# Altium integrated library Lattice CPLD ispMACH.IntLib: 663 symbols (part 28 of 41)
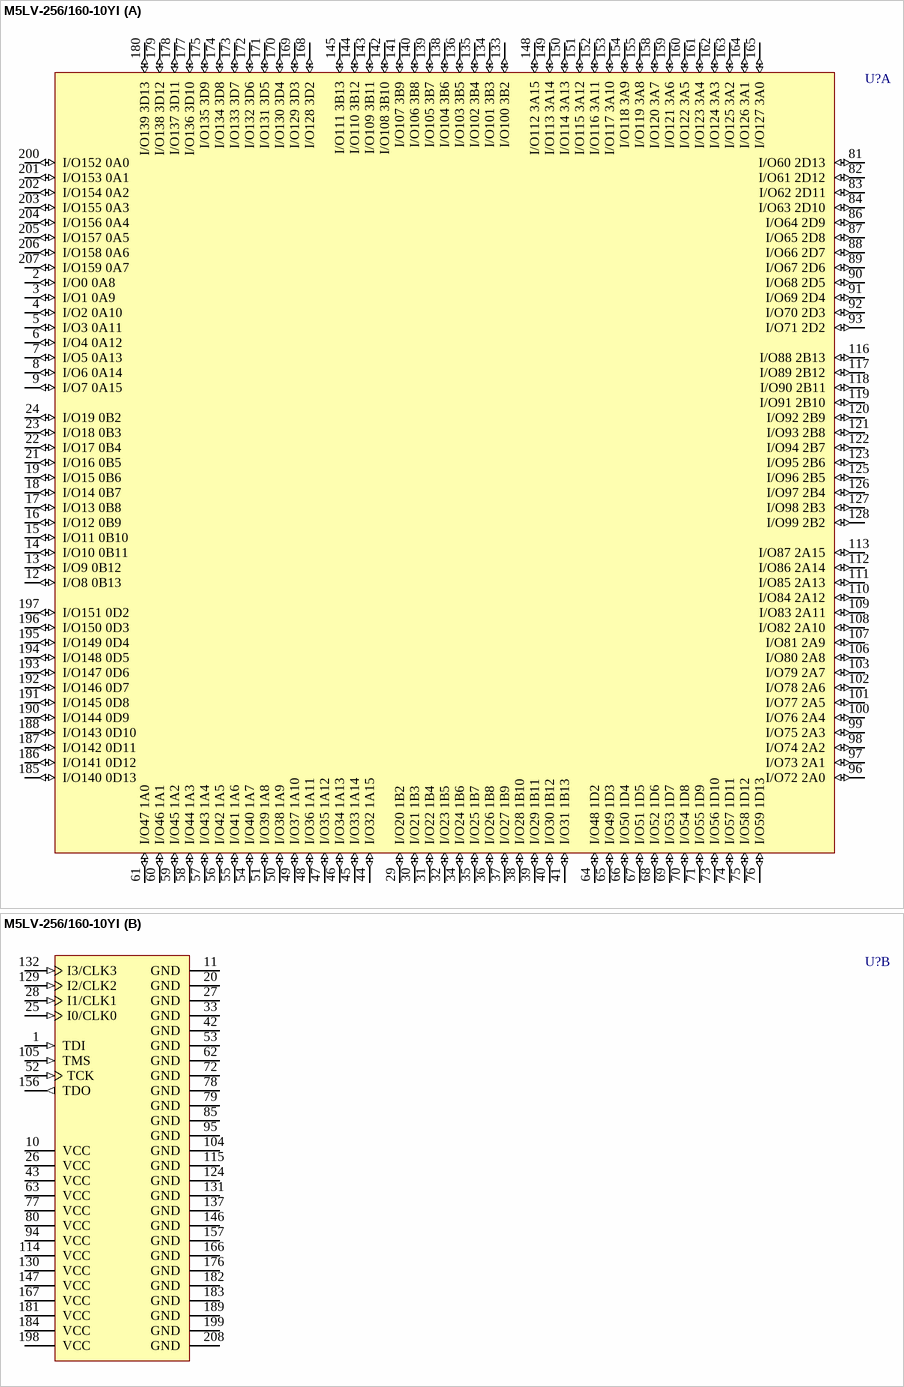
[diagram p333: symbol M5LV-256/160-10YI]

## M5LV-256/160-10YI
designator U?
High-Density and High-I/O Complex PLD
footprint PQFP208_N (Shrink QFP, 208-Leads, Body 28x28mm, Pitch 0.5mm, IPC Medium Density)
footprint PQFP208_L (Shrink QFP, 208-Leads, Body 28x28mm, Pitch 0.5mm, IPC High Density)
footprint PQFP208_M (Shrink QFP, 208-Leads, Body 28x28mm, Pitch 0.5mm, IPC Low Density)
3D model M5LV-PQFP208 (208-Pin Plastic Quad Flat Pack (PQFP208))
part A pins: 2 I/O0 0A8 (io), 3 I/O1 0A9 (io), 4 I/O2 0A10 (io), 5 I/O3 0A11 (io), 6 I/O4 0A12 (io), 7 I/O5 0A13 (io), 8 I/O6 0A14 (io), 9 I/O7 0A15 (io), 12 I/O8 0B13 (io), 13 I/O9 0B12 (io), 14 I/O10 0B11 (io), 15 I/O11 0B10 (io), 16 I/O12 0B9 (io), 17 I/O13 0B8 (io), 18 I/O14 0B7 (io), 19 I/O15 0B6 (io), 21 I/O16 0B5 (io), 22 I/O17 0B4 (io), 23 I/O18 0B3 (io), 24 I/O19 0B2 (io), 29 I/O20 1B2 (io), 30 I/O21 1B3 (io), 31 I/O22 1B4 (io), 32 I/O23 1B5 (io), 34 I/O24 1B6 (io), 35 I/O25 1B7 (io), 36 I/O26 1B8 (io), 37 I/O27 1B9 (io), 38 I/O28 1B10 (io), 39 I/O29 1B11 (io), 40 I/O30 1B12 (io), 41 I/O31 1B13 (io), 44 I/O32 1A15 (io), 45 I/O33 1A14 (io), 46 I/O34 1A13 (io), 47 I/O35 1A12 (io), 48 I/O36 1A11 (io), 49 I/O37 1A10 (io), 50 I/O38 1A9 (io), 51 I/O39 1A8 (io), 54 I/O40 1A7 (io), 55 I/O41 1A6 (io), 56 I/O42 1A5 (io), 57 I/O43 1A4 (io), 58 I/O44 1A3 (io), 59 I/O45 1A2 (io), 60 I/O46 1A1 (io), 61 I/O47 1A0 (io), 64 I/O48 1D2 (io), 65 I/O49 1D3 (io), 66 I/O50 1D4 (io), 67 I/O51 1D5 (io), 68 I/O52 1D6 (io), 69 I/O53 1D7 (io), 70 I/O54 1D8 (io), 71 I/O55 1D9 (io), 73 I/O56 1D10 (io), 74 I/O57 1D11 (io), 75 I/O58 1D12 (io), 76 I/O59 1D13 (io), 81 I/O60 2D13 (io), 82 I/O61 2D12 (io), 83 I/O62 2D11 (io), 84 I/O63 2D10 (io), 86 I/O64 2D9 (io), 87 I/O65 2D8 (io), 88 I/O66 2D7 (io), 89 I/O67 2D6 (io), 90 I/O68 2D5 (io), 91 I/O69 2D4 (io), 92 I/O70 2D3 (io), 93 I/O71 2D2 (io), 96 I/O72 2A0 (io), 97 I/O73 2A1 (io), 98 I/O74 2A2 (io), 99 I/O75 2A3 (io), 100 I/O76 2A4 (io), 101 I/O77 2A5 (io), 102 I/O78 2A6 (io), 103 I/O79 2A7 (io), 106 I/O80 2A8 (io), 107 I/O81 2A9 (io), 108 I/O82 2A10 (io), 109 I/O83 2A11 (io), 110 I/O84 2A12 (io), 111 I/O85 2A13 (io), 112 I/O86 2A14 (io), 113 I/O87 2A15 (io), 116 I/O88 2B13 (io), 117 I/O89 2B12 (io), 118 I/O90 2B11 (io), 119 I/O91 2B10 (io), 120 I/O92 2B9 (io), 121 I/O93 2B8 (io), 122 I/O94 2B7 (io), 123 I/O95 2B6 (io), 125 I/O96 2B5 (io), 126 I/O97 2B4 (io), 127 I/O98 2B3 (io), 128 I/O99 2B2 (io), 133 I/O100 3B2 (io), 134 I/O101 3B3 (io), 135 I/O102 3B4 (io), 136 I/O103 3B5 (io), 138 I/O104 3B6 (io), 139 I/O105 3B7 (io), 140 I/O106 3B8 (io), 141 I/O107 3B9 (io), 142 I/O108 3B10 (io), 143 I/O109 3B11 (io), 144 I/O110 3B12 (io), 145 I/O111 3B13 (io), 148 I/O112 3A15 (io), 149 I/O113 3A14 (io), 150 I/O114 3A13 (io), 151 I/O115 3A12 (io), 152 I/O116 3A11 (io), 153 I/O117 3A10 (io), 154 I/O118 3A9 (io), 155 I/O119 3A8 (io), 158 I/O120 3A7 (io), 159 I/O121 3A6 (io), 160 I/O122 3A5 (io), 161 I/O123 3A4 (io), 162 I/O124 3A3 (io), 163 I/O125 3A2 (io), 164 I/O126 3A1 (io), 165 I/O127 3A0 (io), 168 I/O128 3D2 (io), 169 I/O129 3D3 (io), 170 I/O130 3D4 (io), 171 I/O131 3D5 (io), 172 I/O132 3D6 (io), 173 I/O133 3D7 (io), 174 I/O134 3D8 (io), 175 I/O135 3D9 (io), 177 I/O136 3D10 (io), 178 I/O137 3D11 (io), 179 I/O138 3D12 (io), 180 I/O139 3D13 (io), 185 I/O140 0D13 (io), 186 I/O141 0D12 (io), 187 I/O142 0D11 (io), 188 I/O143 0D10 (io), 190 I/O144 0D9 (io), 191 I/O145 0D8 (io), 192 I/O146 0D7 (io), 193 I/O147 0D6 (io), 194 I/O148 0D5 (io), 195 I/O149 0D4 (io), 196 I/O150 0D3 (io), 197 I/O151 0D2 (io), 200 I/O152 0A0 (io), 201 I/O153 0A1 (io), 202 I/O154 0A2 (io), 203 I/O155 0A3 (io), 204 I/O156 0A4 (io), 205 I/O157 0A5 (io), 206 I/O158 0A6 (io), 207 I/O159 0A7 (io)
part B pins: 1 TDI (in), 10 VCC (power), 11 GND (power), 20 GND (power), 25 I0/CLK0 (in), 26 VCC (power), 27 GND (power), 28 I1/CLK1 (in), 33 GND (power), 42 GND (power), 43 VCC (power), 52 TCK (in), 53 GND (power), 62 GND (power), 63 VCC (power), 72 GND (power), 77 VCC (power), 78 GND (power), 79 GND (power), 80 VCC (power), 85 GND (power), 94 VCC (power), 95 GND (power), 104 GND (power), 105 TMS (in), 114 VCC (power), 115 GND (power), 124 GND (power), 129 I2/CLK2 (in), 130 VCC (power), 131 GND (power), 132 I3/CLK3 (in), 137 GND (power), 146 GND (power), 147 VCC (power), 156 TDO (out), 157 GND (power), 166 GND (power), 167 VCC (power), 176 GND (power), 181 VCC (power), 182 GND (power), 183 GND (power), 184 VCC (power), 189 GND (power), 198 VCC (power), 199 GND (power), 208 GND (power)

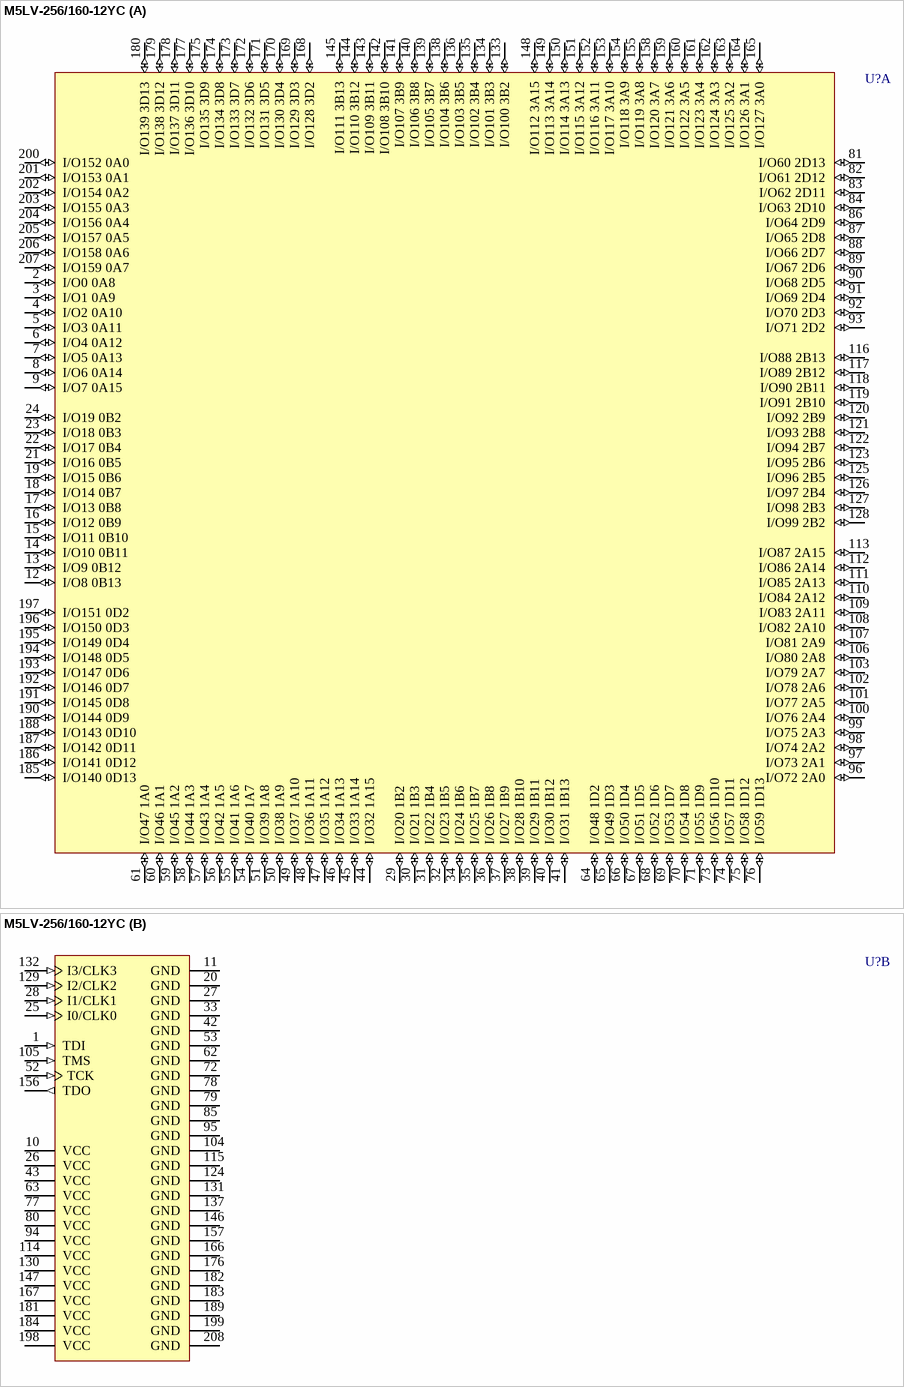
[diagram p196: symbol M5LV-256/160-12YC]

## M5LV-256/160-12YC
designator U?
High-Density and High-I/O Complex PLD
footprint PQFP208_N (Shrink QFP, 208-Leads, Body 28x28mm, Pitch 0.5mm, IPC Medium Density)
footprint PQFP208_L (Shrink QFP, 208-Leads, Body 28x28mm, Pitch 0.5mm, IPC High Density)
footprint PQFP208_M (Shrink QFP, 208-Leads, Body 28x28mm, Pitch 0.5mm, IPC Low Density)
3D model M5LV-PQFP208 (208-Pin Plastic Quad Flat Pack (PQFP208))
part A pins: 2 I/O0 0A8 (io), 3 I/O1 0A9 (io), 4 I/O2 0A10 (io), 5 I/O3 0A11 (io), 6 I/O4 0A12 (io), 7 I/O5 0A13 (io), 8 I/O6 0A14 (io), 9 I/O7 0A15 (io), 12 I/O8 0B13 (io), 13 I/O9 0B12 (io), 14 I/O10 0B11 (io), 15 I/O11 0B10 (io), 16 I/O12 0B9 (io), 17 I/O13 0B8 (io), 18 I/O14 0B7 (io), 19 I/O15 0B6 (io), 21 I/O16 0B5 (io), 22 I/O17 0B4 (io), 23 I/O18 0B3 (io), 24 I/O19 0B2 (io), 29 I/O20 1B2 (io), 30 I/O21 1B3 (io), 31 I/O22 1B4 (io), 32 I/O23 1B5 (io), 34 I/O24 1B6 (io), 35 I/O25 1B7 (io), 36 I/O26 1B8 (io), 37 I/O27 1B9 (io), 38 I/O28 1B10 (io), 39 I/O29 1B11 (io), 40 I/O30 1B12 (io), 41 I/O31 1B13 (io), 44 I/O32 1A15 (io), 45 I/O33 1A14 (io), 46 I/O34 1A13 (io), 47 I/O35 1A12 (io), 48 I/O36 1A11 (io), 49 I/O37 1A10 (io), 50 I/O38 1A9 (io), 51 I/O39 1A8 (io), 54 I/O40 1A7 (io), 55 I/O41 1A6 (io), 56 I/O42 1A5 (io), 57 I/O43 1A4 (io), 58 I/O44 1A3 (io), 59 I/O45 1A2 (io), 60 I/O46 1A1 (io), 61 I/O47 1A0 (io), 64 I/O48 1D2 (io), 65 I/O49 1D3 (io), 66 I/O50 1D4 (io), 67 I/O51 1D5 (io), 68 I/O52 1D6 (io), 69 I/O53 1D7 (io), 70 I/O54 1D8 (io), 71 I/O55 1D9 (io), 73 I/O56 1D10 (io), 74 I/O57 1D11 (io), 75 I/O58 1D12 (io), 76 I/O59 1D13 (io), 81 I/O60 2D13 (io), 82 I/O61 2D12 (io), 83 I/O62 2D11 (io), 84 I/O63 2D10 (io), 86 I/O64 2D9 (io), 87 I/O65 2D8 (io), 88 I/O66 2D7 (io), 89 I/O67 2D6 (io), 90 I/O68 2D5 (io), 91 I/O69 2D4 (io), 92 I/O70 2D3 (io), 93 I/O71 2D2 (io), 96 I/O72 2A0 (io), 97 I/O73 2A1 (io), 98 I/O74 2A2 (io), 99 I/O75 2A3 (io), 100 I/O76 2A4 (io), 101 I/O77 2A5 (io), 102 I/O78 2A6 (io), 103 I/O79 2A7 (io), 106 I/O80 2A8 (io), 107 I/O81 2A9 (io), 108 I/O82 2A10 (io), 109 I/O83 2A11 (io), 110 I/O84 2A12 (io), 111 I/O85 2A13 (io), 112 I/O86 2A14 (io), 113 I/O87 2A15 (io), 116 I/O88 2B13 (io), 117 I/O89 2B12 (io), 118 I/O90 2B11 (io), 119 I/O91 2B10 (io), 120 I/O92 2B9 (io), 121 I/O93 2B8 (io), 122 I/O94 2B7 (io), 123 I/O95 2B6 (io), 125 I/O96 2B5 (io), 126 I/O97 2B4 (io), 127 I/O98 2B3 (io), 128 I/O99 2B2 (io), 133 I/O100 3B2 (io), 134 I/O101 3B3 (io), 135 I/O102 3B4 (io), 136 I/O103 3B5 (io), 138 I/O104 3B6 (io), 139 I/O105 3B7 (io), 140 I/O106 3B8 (io), 141 I/O107 3B9 (io), 142 I/O108 3B10 (io), 143 I/O109 3B11 (io), 144 I/O110 3B12 (io), 145 I/O111 3B13 (io), 148 I/O112 3A15 (io), 149 I/O113 3A14 (io), 150 I/O114 3A13 (io), 151 I/O115 3A12 (io), 152 I/O116 3A11 (io), 153 I/O117 3A10 (io), 154 I/O118 3A9 (io), 155 I/O119 3A8 (io), 158 I/O120 3A7 (io), 159 I/O121 3A6 (io), 160 I/O122 3A5 (io), 161 I/O123 3A4 (io), 162 I/O124 3A3 (io), 163 I/O125 3A2 (io), 164 I/O126 3A1 (io), 165 I/O127 3A0 (io), 168 I/O128 3D2 (io), 169 I/O129 3D3 (io), 170 I/O130 3D4 (io), 171 I/O131 3D5 (io), 172 I/O132 3D6 (io), 173 I/O133 3D7 (io), 174 I/O134 3D8 (io), 175 I/O135 3D9 (io), 177 I/O136 3D10 (io), 178 I/O137 3D11 (io), 179 I/O138 3D12 (io), 180 I/O139 3D13 (io), 185 I/O140 0D13 (io), 186 I/O141 0D12 (io), 187 I/O142 0D11 (io), 188 I/O143 0D10 (io), 190 I/O144 0D9 (io), 191 I/O145 0D8 (io), 192 I/O146 0D7 (io), 193 I/O147 0D6 (io), 194 I/O148 0D5 (io), 195 I/O149 0D4 (io), 196 I/O150 0D3 (io), 197 I/O151 0D2 (io), 200 I/O152 0A0 (io), 201 I/O153 0A1 (io), 202 I/O154 0A2 (io), 203 I/O155 0A3 (io), 204 I/O156 0A4 (io), 205 I/O157 0A5 (io), 206 I/O158 0A6 (io), 207 I/O159 0A7 (io)
part B pins: 1 TDI (in), 10 VCC (power), 11 GND (power), 20 GND (power), 25 I0/CLK0 (in), 26 VCC (power), 27 GND (power), 28 I1/CLK1 (in), 33 GND (power), 42 GND (power), 43 VCC (power), 52 TCK (in), 53 GND (power), 62 GND (power), 63 VCC (power), 72 GND (power), 77 VCC (power), 78 GND (power), 79 GND (power), 80 VCC (power), 85 GND (power), 94 VCC (power), 95 GND (power), 104 GND (power), 105 TMS (in), 114 VCC (power), 115 GND (power), 124 GND (power), 129 I2/CLK2 (in), 130 VCC (power), 131 GND (power), 132 I3/CLK3 (in), 137 GND (power), 146 GND (power), 147 VCC (power), 156 TDO (out), 157 GND (power), 166 GND (power), 167 VCC (power), 176 GND (power), 181 VCC (power), 182 GND (power), 183 GND (power), 184 VCC (power), 189 GND (power), 198 VCC (power), 199 GND (power), 208 GND (power)

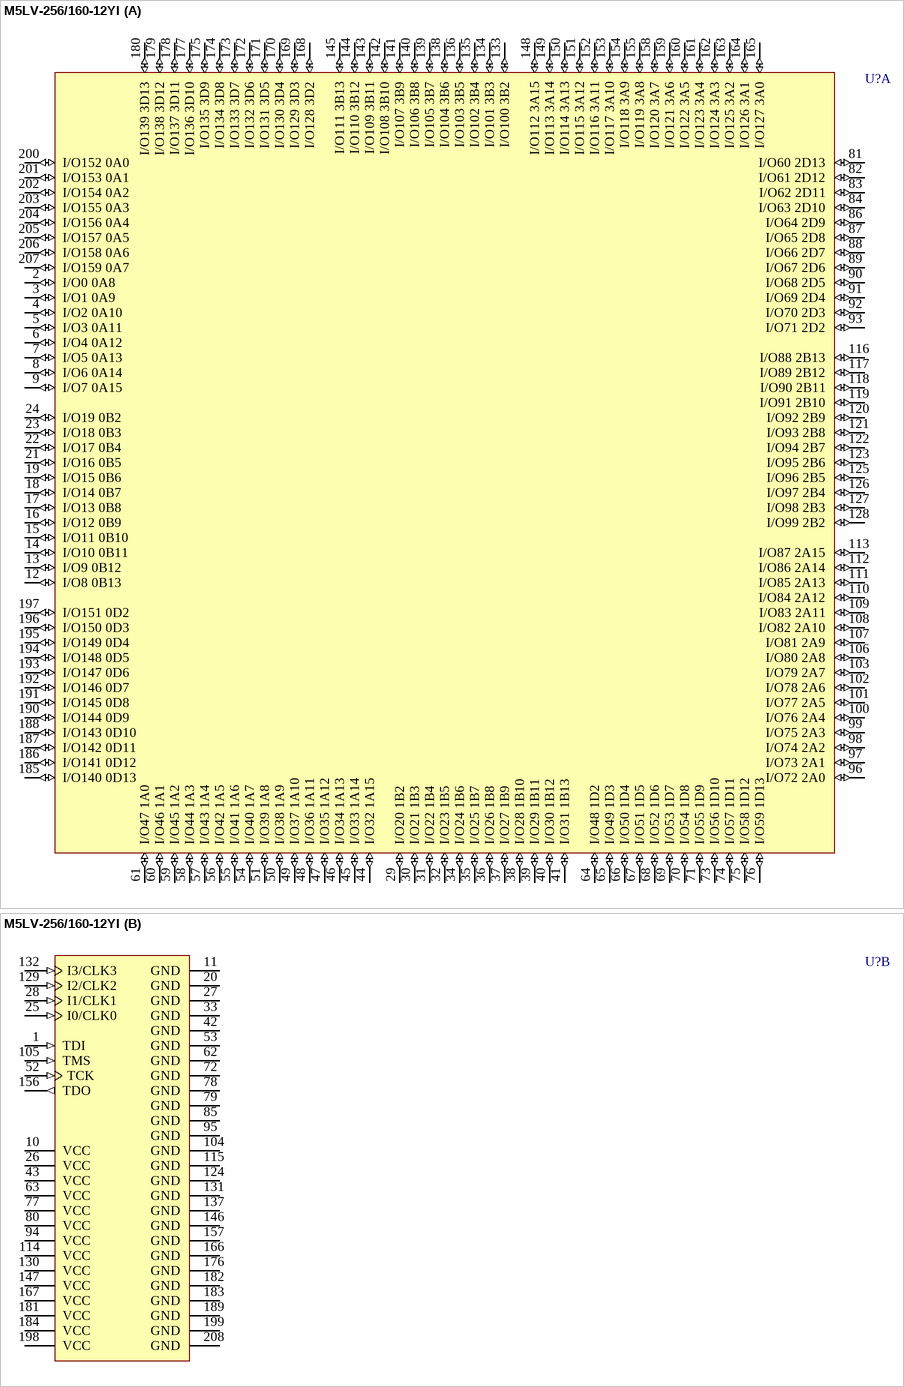
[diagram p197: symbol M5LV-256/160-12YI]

## M5LV-256/160-12YI
designator U?
High-Density and High-I/O Complex PLD
footprint PQFP208_N (Shrink QFP, 208-Leads, Body 28x28mm, Pitch 0.5mm, IPC Medium Density)
footprint PQFP208_L (Shrink QFP, 208-Leads, Body 28x28mm, Pitch 0.5mm, IPC High Density)
footprint PQFP208_M (Shrink QFP, 208-Leads, Body 28x28mm, Pitch 0.5mm, IPC Low Density)
3D model M5LV-PQFP208 (208-Pin Plastic Quad Flat Pack (PQFP208))
part A pins: 2 I/O0 0A8 (io), 3 I/O1 0A9 (io), 4 I/O2 0A10 (io), 5 I/O3 0A11 (io), 6 I/O4 0A12 (io), 7 I/O5 0A13 (io), 8 I/O6 0A14 (io), 9 I/O7 0A15 (io), 12 I/O8 0B13 (io), 13 I/O9 0B12 (io), 14 I/O10 0B11 (io), 15 I/O11 0B10 (io), 16 I/O12 0B9 (io), 17 I/O13 0B8 (io), 18 I/O14 0B7 (io), 19 I/O15 0B6 (io), 21 I/O16 0B5 (io), 22 I/O17 0B4 (io), 23 I/O18 0B3 (io), 24 I/O19 0B2 (io), 29 I/O20 1B2 (io), 30 I/O21 1B3 (io), 31 I/O22 1B4 (io), 32 I/O23 1B5 (io), 34 I/O24 1B6 (io), 35 I/O25 1B7 (io), 36 I/O26 1B8 (io), 37 I/O27 1B9 (io), 38 I/O28 1B10 (io), 39 I/O29 1B11 (io), 40 I/O30 1B12 (io), 41 I/O31 1B13 (io), 44 I/O32 1A15 (io), 45 I/O33 1A14 (io), 46 I/O34 1A13 (io), 47 I/O35 1A12 (io), 48 I/O36 1A11 (io), 49 I/O37 1A10 (io), 50 I/O38 1A9 (io), 51 I/O39 1A8 (io), 54 I/O40 1A7 (io), 55 I/O41 1A6 (io), 56 I/O42 1A5 (io), 57 I/O43 1A4 (io), 58 I/O44 1A3 (io), 59 I/O45 1A2 (io), 60 I/O46 1A1 (io), 61 I/O47 1A0 (io), 64 I/O48 1D2 (io), 65 I/O49 1D3 (io), 66 I/O50 1D4 (io), 67 I/O51 1D5 (io), 68 I/O52 1D6 (io), 69 I/O53 1D7 (io), 70 I/O54 1D8 (io), 71 I/O55 1D9 (io), 73 I/O56 1D10 (io), 74 I/O57 1D11 (io), 75 I/O58 1D12 (io), 76 I/O59 1D13 (io), 81 I/O60 2D13 (io), 82 I/O61 2D12 (io), 83 I/O62 2D11 (io), 84 I/O63 2D10 (io), 86 I/O64 2D9 (io), 87 I/O65 2D8 (io), 88 I/O66 2D7 (io), 89 I/O67 2D6 (io), 90 I/O68 2D5 (io), 91 I/O69 2D4 (io), 92 I/O70 2D3 (io), 93 I/O71 2D2 (io), 96 I/O72 2A0 (io), 97 I/O73 2A1 (io), 98 I/O74 2A2 (io), 99 I/O75 2A3 (io), 100 I/O76 2A4 (io), 101 I/O77 2A5 (io), 102 I/O78 2A6 (io), 103 I/O79 2A7 (io), 106 I/O80 2A8 (io), 107 I/O81 2A9 (io), 108 I/O82 2A10 (io), 109 I/O83 2A11 (io), 110 I/O84 2A12 (io), 111 I/O85 2A13 (io), 112 I/O86 2A14 (io), 113 I/O87 2A15 (io), 116 I/O88 2B13 (io), 117 I/O89 2B12 (io), 118 I/O90 2B11 (io), 119 I/O91 2B10 (io), 120 I/O92 2B9 (io), 121 I/O93 2B8 (io), 122 I/O94 2B7 (io), 123 I/O95 2B6 (io), 125 I/O96 2B5 (io), 126 I/O97 2B4 (io), 127 I/O98 2B3 (io), 128 I/O99 2B2 (io), 133 I/O100 3B2 (io), 134 I/O101 3B3 (io), 135 I/O102 3B4 (io), 136 I/O103 3B5 (io), 138 I/O104 3B6 (io), 139 I/O105 3B7 (io), 140 I/O106 3B8 (io), 141 I/O107 3B9 (io), 142 I/O108 3B10 (io), 143 I/O109 3B11 (io), 144 I/O110 3B12 (io), 145 I/O111 3B13 (io), 148 I/O112 3A15 (io), 149 I/O113 3A14 (io), 150 I/O114 3A13 (io), 151 I/O115 3A12 (io), 152 I/O116 3A11 (io), 153 I/O117 3A10 (io), 154 I/O118 3A9 (io), 155 I/O119 3A8 (io), 158 I/O120 3A7 (io), 159 I/O121 3A6 (io), 160 I/O122 3A5 (io), 161 I/O123 3A4 (io), 162 I/O124 3A3 (io), 163 I/O125 3A2 (io), 164 I/O126 3A1 (io), 165 I/O127 3A0 (io), 168 I/O128 3D2 (io), 169 I/O129 3D3 (io), 170 I/O130 3D4 (io), 171 I/O131 3D5 (io), 172 I/O132 3D6 (io), 173 I/O133 3D7 (io), 174 I/O134 3D8 (io), 175 I/O135 3D9 (io), 177 I/O136 3D10 (io), 178 I/O137 3D11 (io), 179 I/O138 3D12 (io), 180 I/O139 3D13 (io), 185 I/O140 0D13 (io), 186 I/O141 0D12 (io), 187 I/O142 0D11 (io), 188 I/O143 0D10 (io), 190 I/O144 0D9 (io), 191 I/O145 0D8 (io), 192 I/O146 0D7 (io), 193 I/O147 0D6 (io), 194 I/O148 0D5 (io), 195 I/O149 0D4 (io), 196 I/O150 0D3 (io), 197 I/O151 0D2 (io), 200 I/O152 0A0 (io), 201 I/O153 0A1 (io), 202 I/O154 0A2 (io), 203 I/O155 0A3 (io), 204 I/O156 0A4 (io), 205 I/O157 0A5 (io), 206 I/O158 0A6 (io), 207 I/O159 0A7 (io)
part B pins: 1 TDI (in), 10 VCC (power), 11 GND (power), 20 GND (power), 25 I0/CLK0 (in), 26 VCC (power), 27 GND (power), 28 I1/CLK1 (in), 33 GND (power), 42 GND (power), 43 VCC (power), 52 TCK (in), 53 GND (power), 62 GND (power), 63 VCC (power), 72 GND (power), 77 VCC (power), 78 GND (power), 79 GND (power), 80 VCC (power), 85 GND (power), 94 VCC (power), 95 GND (power), 104 GND (power), 105 TMS (in), 114 VCC (power), 115 GND (power), 124 GND (power), 129 I2/CLK2 (in), 130 VCC (power), 131 GND (power), 132 I3/CLK3 (in), 137 GND (power), 146 GND (power), 147 VCC (power), 156 TDO (out), 157 GND (power), 166 GND (power), 167 VCC (power), 176 GND (power), 181 VCC (power), 182 GND (power), 183 GND (power), 184 VCC (power), 189 GND (power), 198 VCC (power), 199 GND (power), 208 GND (power)

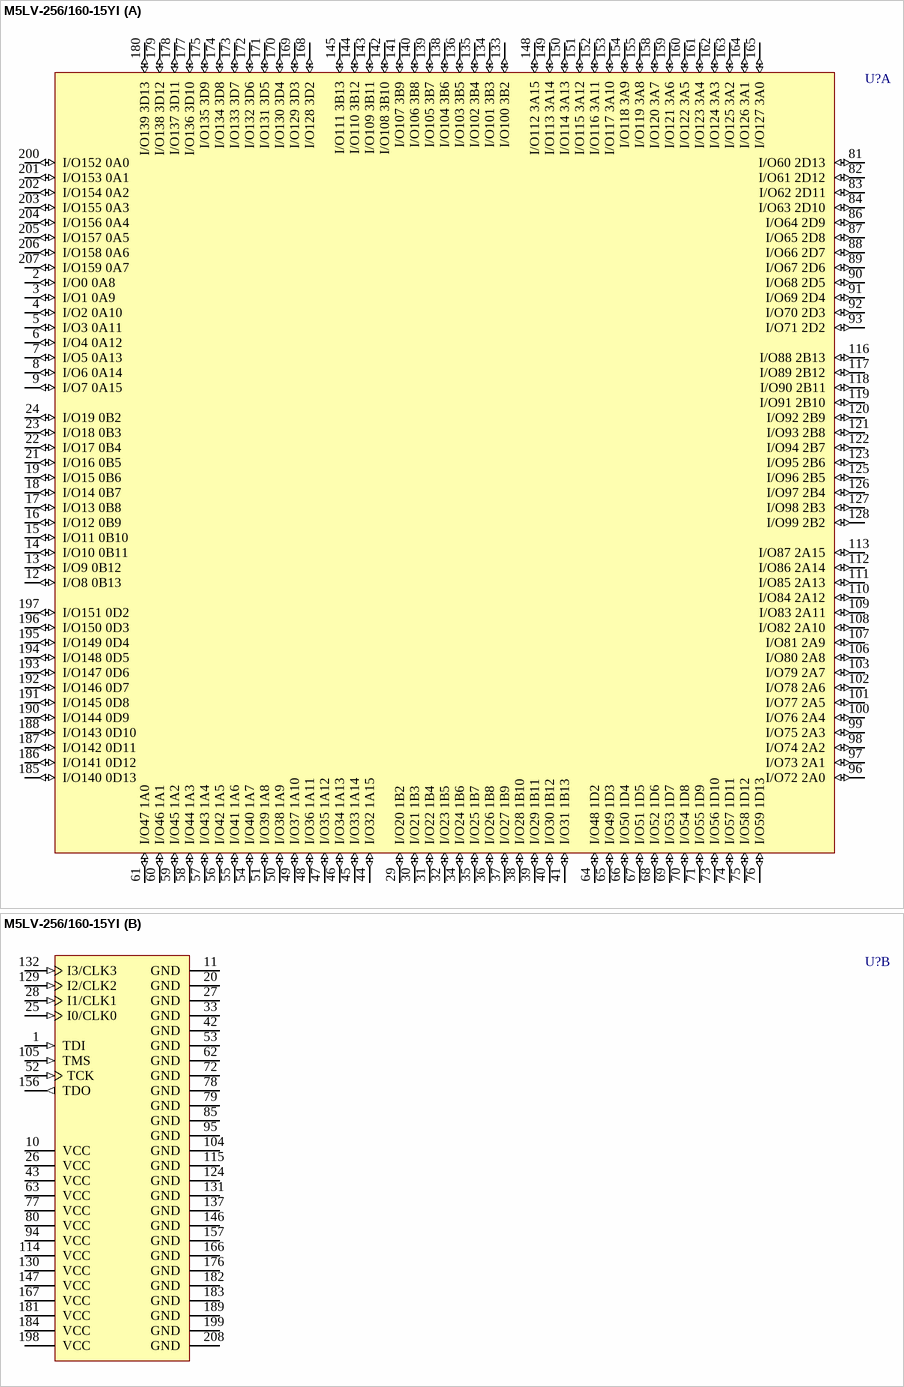
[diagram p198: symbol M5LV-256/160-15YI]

## M5LV-256/160-15YI
designator U?
High-Density and High-I/O Complex PLD
footprint PQFP208_N (Shrink QFP, 208-Leads, Body 28x28mm, Pitch 0.5mm, IPC Medium Density)
footprint PQFP208_L (Shrink QFP, 208-Leads, Body 28x28mm, Pitch 0.5mm, IPC High Density)
footprint PQFP208_M (Shrink QFP, 208-Leads, Body 28x28mm, Pitch 0.5mm, IPC Low Density)
3D model M5LV-PQFP208 (208-Pin Plastic Quad Flat Pack (PQFP208))
part A pins: 2 I/O0 0A8 (io), 3 I/O1 0A9 (io), 4 I/O2 0A10 (io), 5 I/O3 0A11 (io), 6 I/O4 0A12 (io), 7 I/O5 0A13 (io), 8 I/O6 0A14 (io), 9 I/O7 0A15 (io), 12 I/O8 0B13 (io), 13 I/O9 0B12 (io), 14 I/O10 0B11 (io), 15 I/O11 0B10 (io), 16 I/O12 0B9 (io), 17 I/O13 0B8 (io), 18 I/O14 0B7 (io), 19 I/O15 0B6 (io), 21 I/O16 0B5 (io), 22 I/O17 0B4 (io), 23 I/O18 0B3 (io), 24 I/O19 0B2 (io), 29 I/O20 1B2 (io), 30 I/O21 1B3 (io), 31 I/O22 1B4 (io), 32 I/O23 1B5 (io), 34 I/O24 1B6 (io), 35 I/O25 1B7 (io), 36 I/O26 1B8 (io), 37 I/O27 1B9 (io), 38 I/O28 1B10 (io), 39 I/O29 1B11 (io), 40 I/O30 1B12 (io), 41 I/O31 1B13 (io), 44 I/O32 1A15 (io), 45 I/O33 1A14 (io), 46 I/O34 1A13 (io), 47 I/O35 1A12 (io), 48 I/O36 1A11 (io), 49 I/O37 1A10 (io), 50 I/O38 1A9 (io), 51 I/O39 1A8 (io), 54 I/O40 1A7 (io), 55 I/O41 1A6 (io), 56 I/O42 1A5 (io), 57 I/O43 1A4 (io), 58 I/O44 1A3 (io), 59 I/O45 1A2 (io), 60 I/O46 1A1 (io), 61 I/O47 1A0 (io), 64 I/O48 1D2 (io), 65 I/O49 1D3 (io), 66 I/O50 1D4 (io), 67 I/O51 1D5 (io), 68 I/O52 1D6 (io), 69 I/O53 1D7 (io), 70 I/O54 1D8 (io), 71 I/O55 1D9 (io), 73 I/O56 1D10 (io), 74 I/O57 1D11 (io), 75 I/O58 1D12 (io), 76 I/O59 1D13 (io), 81 I/O60 2D13 (io), 82 I/O61 2D12 (io), 83 I/O62 2D11 (io), 84 I/O63 2D10 (io), 86 I/O64 2D9 (io), 87 I/O65 2D8 (io), 88 I/O66 2D7 (io), 89 I/O67 2D6 (io), 90 I/O68 2D5 (io), 91 I/O69 2D4 (io), 92 I/O70 2D3 (io), 93 I/O71 2D2 (io), 96 I/O72 2A0 (io), 97 I/O73 2A1 (io), 98 I/O74 2A2 (io), 99 I/O75 2A3 (io), 100 I/O76 2A4 (io), 101 I/O77 2A5 (io), 102 I/O78 2A6 (io), 103 I/O79 2A7 (io), 106 I/O80 2A8 (io), 107 I/O81 2A9 (io), 108 I/O82 2A10 (io), 109 I/O83 2A11 (io), 110 I/O84 2A12 (io), 111 I/O85 2A13 (io), 112 I/O86 2A14 (io), 113 I/O87 2A15 (io), 116 I/O88 2B13 (io), 117 I/O89 2B12 (io), 118 I/O90 2B11 (io), 119 I/O91 2B10 (io), 120 I/O92 2B9 (io), 121 I/O93 2B8 (io), 122 I/O94 2B7 (io), 123 I/O95 2B6 (io), 125 I/O96 2B5 (io), 126 I/O97 2B4 (io), 127 I/O98 2B3 (io), 128 I/O99 2B2 (io), 133 I/O100 3B2 (io), 134 I/O101 3B3 (io), 135 I/O102 3B4 (io), 136 I/O103 3B5 (io), 138 I/O104 3B6 (io), 139 I/O105 3B7 (io), 140 I/O106 3B8 (io), 141 I/O107 3B9 (io), 142 I/O108 3B10 (io), 143 I/O109 3B11 (io), 144 I/O110 3B12 (io), 145 I/O111 3B13 (io), 148 I/O112 3A15 (io), 149 I/O113 3A14 (io), 150 I/O114 3A13 (io), 151 I/O115 3A12 (io), 152 I/O116 3A11 (io), 153 I/O117 3A10 (io), 154 I/O118 3A9 (io), 155 I/O119 3A8 (io), 158 I/O120 3A7 (io), 159 I/O121 3A6 (io), 160 I/O122 3A5 (io), 161 I/O123 3A4 (io), 162 I/O124 3A3 (io), 163 I/O125 3A2 (io), 164 I/O126 3A1 (io), 165 I/O127 3A0 (io), 168 I/O128 3D2 (io), 169 I/O129 3D3 (io), 170 I/O130 3D4 (io), 171 I/O131 3D5 (io), 172 I/O132 3D6 (io), 173 I/O133 3D7 (io), 174 I/O134 3D8 (io), 175 I/O135 3D9 (io), 177 I/O136 3D10 (io), 178 I/O137 3D11 (io), 179 I/O138 3D12 (io), 180 I/O139 3D13 (io), 185 I/O140 0D13 (io), 186 I/O141 0D12 (io), 187 I/O142 0D11 (io), 188 I/O143 0D10 (io), 190 I/O144 0D9 (io), 191 I/O145 0D8 (io), 192 I/O146 0D7 (io), 193 I/O147 0D6 (io), 194 I/O148 0D5 (io), 195 I/O149 0D4 (io), 196 I/O150 0D3 (io), 197 I/O151 0D2 (io), 200 I/O152 0A0 (io), 201 I/O153 0A1 (io), 202 I/O154 0A2 (io), 203 I/O155 0A3 (io), 204 I/O156 0A4 (io), 205 I/O157 0A5 (io), 206 I/O158 0A6 (io), 207 I/O159 0A7 (io)
part B pins: 1 TDI (in), 10 VCC (power), 11 GND (power), 20 GND (power), 25 I0/CLK0 (in), 26 VCC (power), 27 GND (power), 28 I1/CLK1 (in), 33 GND (power), 42 GND (power), 43 VCC (power), 52 TCK (in), 53 GND (power), 62 GND (power), 63 VCC (power), 72 GND (power), 77 VCC (power), 78 GND (power), 79 GND (power), 80 VCC (power), 85 GND (power), 94 VCC (power), 95 GND (power), 104 GND (power), 105 TMS (in), 114 VCC (power), 115 GND (power), 124 GND (power), 129 I2/CLK2 (in), 130 VCC (power), 131 GND (power), 132 I3/CLK3 (in), 137 GND (power), 146 GND (power), 147 VCC (power), 156 TDO (out), 157 GND (power), 166 GND (power), 167 VCC (power), 176 GND (power), 181 VCC (power), 182 GND (power), 183 GND (power), 184 VCC (power), 189 GND (power), 198 VCC (power), 199 GND (power), 208 GND (power)

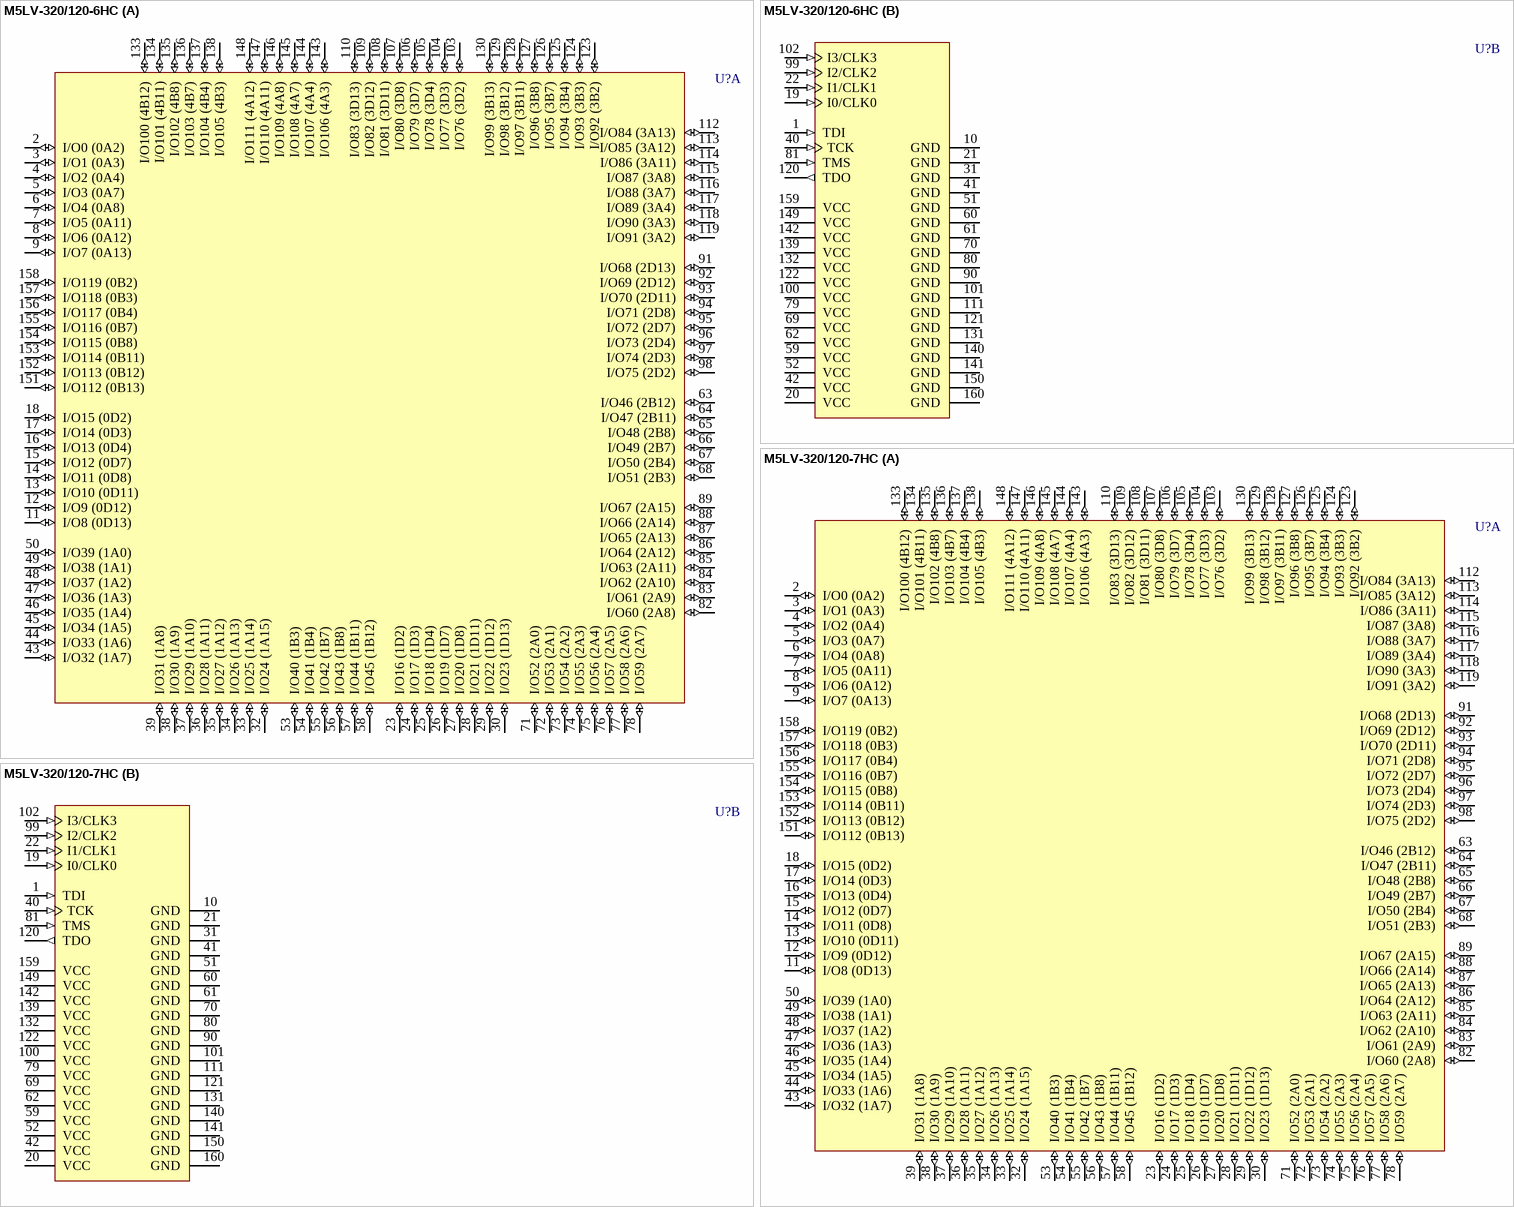
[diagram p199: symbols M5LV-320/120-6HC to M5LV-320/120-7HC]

## M5LV-320/120-6HC
designator U?
High-Density and High-I/O Complex PLD
footprint MQFP160_N (QFP, 160-Leads, Body 27.7 x 27.7mm, Pitch 0.65mm, IPC Medium Density)
footprint MQFP160_L (QFP, 160-Leads, Body 27.7 x 27.7mm, Pitch 0.65mm, IPC High Density)
footprint MQFP160_M (QFP, 160-Leads, Body 27.7 x 27.7mm, Pitch 0.65mm, IPC Low Density)
3D model M5LV-MQFP160 (160-Pin Quad Flat Pack 0.65 mm Pitch)
part A pins: 2 I/O0 (0A2) (io), 3 I/O1 (0A3) (io), 4 I/O2 (0A4) (io), 5 I/O3 (0A7) (io), 6 I/O4 (0A8) (io), 7 I/O5 (0A11) (io), 8 I/O6 (0A12) (io), 9 I/O7 (0A13) (io), 11 I/O8 (0D13) (io), 12 I/O9 (0D12) (io), 13 I/O10 (0D11) (io), 14 I/O11 (0D8) (io), 15 I/O12 (0D7) (io), 16 I/O13 (0D4) (io), 17 I/O14 (0D3) (io), 18 I/O15 (0D2) (io), 23 I/O16 (1D2) (io), 24 I/O17 (1D3) (io), 25 I/O18 (1D4) (io), 26 I/O19 (1D7) (io), 27 I/O20 (1D8) (io), 28 I/O21 (1D11) (io), 29 I/O22 (1D12) (io), 30 I/O23 (1D13) (io), 32 I/O24 (1A15) (io), 33 I/O25 (1A14) (io), 34 I/O26 (1A13) (io), 35 I/O27 (1A12) (io), 36 I/O28 (1A11) (io), 37 I/O29 (1A10) (io), 38 I/O30 (1A9) (io), 39 I/O31 (1A8) (io), 43 I/O32 (1A7) (io), 44 I/O33 (1A6) (io), 45 I/O34 (1A5) (io), 46 I/O35 (1A4) (io), 47 I/O36 (1A3) (io), 48 I/O37 (1A2) (io), 49 I/O38 (1A1) (io), 50 I/O39 (1A0) (io), 53 I/O40 (1B3) (io), 54 I/O41 (1B4) (io), 55 I/O42 (1B7) (io), 56 I/O43 (1B8) (io), 57 I/O44 (1B11) (io), 58 I/O45 (1B12) (io), 63 I/O46 (2B12) (io), 64 I/O47 (2B11) (io), 65 I/O48 (2B8) (io), 66 I/O49 (2B7) (io), 67 I/O50 (2B4) (io), 68 I/O51 (2B3) (io), 71 I/O52 (2A0) (io), 72 I/O53 (2A1) (io), 73 I/O54 (2A2) (io), 74 I/O55 (2A3) (io), 75 I/O56 (2A4) (io), 76 I/O57 (2A5) (io), 77 I/O58 (2A6) (io), 78 I/O59 (2A7) (io), 82 I/O60 (2A8) (io), 83 I/O61 (2A9) (io), 84 I/O62 (2A10) (io), 85 I/O63 (2A11) (io), 86 I/O64 (2A12) (io), 87 I/O65 (2A13) (io), 88 I/O66 (2A14) (io), 89 I/O67 (2A15) (io), 91 I/O68 (2D13) (io), 92 I/O69 (2D12) (io), 93 I/O70 (2D11) (io), 94 I/O71 (2D8) (io), 95 I/O72 (2D7) (io), 96 I/O73 (2D4) (io), 97 I/O74 (2D3) (io), 98 I/O75 (2D2) (io), 103 I/O76 (3D2) (io), 104 I/O77 (3D3) (io), 105 I/O78 (3D4) (io), 106 I/O79 (3D7) (io), 107 I/O80 (3D8) (io), 108 I/O81 (3D11) (io), 109 I/O82 (3D12) (io), 110 I/O83 (3D13) (io), 112 I/O84 (3A13) (io), 113 I/O85 (3A12) (io), 114 I/O86 (3A11) (io), 115 I/O87 (3A8) (io), 116 I/O88 (3A7) (io), 117 I/O89 (3A4) (io), 118 I/O90 (3A3) (io), 119 I/O91 (3A2) (io), 123 I/O92 (3B2) (io), 124 I/O93 (3B3) (io), 125 I/O94 (3B4) (io), 126 I/O95 (3B7) (io), 127 I/O96 (3B8) (io), 128 I/O97 (3B11) (io), 129 I/O98 (3B12) (io), 130 I/O99 (3B13) (io), 133 I/O100 (4B12) (io), 134 I/O101 (4B11) (io), 135 I/O102 (4B8) (io), 136 I/O103 (4B7) (io), 137 I/O104 (4B4) (io), 138 I/O105 (4B3) (io), 143 I/O106 (4A3) (io), 144 I/O107 (4A4) (io), 145 I/O108 (4A7) (io), 146 I/O109 (4A8) (io), 147 I/O110 (4A11) (io), 148 I/O111 (4A12) (io), 151 I/O112 (0B13) (io), 152 I/O113 (0B12) (io), 153 I/O114 (0B11) (io), 154 I/O115 (0B8) (io), 155 I/O116 (0B7) (io), 156 I/O117 (0B4) (io), 157 I/O118 (0B3) (io), 158 I/O119 (0B2) (io)
part B pins: 1 TDI (in), 10 GND (power), 19 I0/CLK0 (in), 20 VCC (power), 21 GND (power), 22 I1/CLK1 (in), 31 GND (power), 40 TCK (in), 41 GND (power), 42 VCC (power), 51 GND (power), 52 VCC (power), 59 VCC (power), 60 GND (power), 61 GND (power), 62 VCC (power), 69 VCC (power), 70 GND (power), 79 VCC (power), 80 GND (power), 81 TMS (in), 90 GND (power), 99 I2/CLK2 (in), 100 VCC (power), 101 GND (power), 102 I3/CLK3 (in), 111 GND (power), 120 TDO (out), 121 GND (power), 122 VCC (power), 131 GND (power), 132 VCC (power), 139 VCC (power), 140 GND (power), 141 GND (power), 142 VCC (power), 149 VCC (power), 150 GND (power), 159 VCC (power), 160 GND (power)

## M5LV-320/120-7HC
designator U?
High-Density and High-I/O Complex PLD
footprint MQFP160_N (QFP, 160-Leads, Body 27.7 x 27.7mm, Pitch 0.65mm, IPC Medium Density)
footprint MQFP160_L (QFP, 160-Leads, Body 27.7 x 27.7mm, Pitch 0.65mm, IPC High Density)
footprint MQFP160_M (QFP, 160-Leads, Body 27.7 x 27.7mm, Pitch 0.65mm, IPC Low Density)
3D model M5LV-MQFP160 (160-Pin Quad Flat Pack 0.65 mm Pitch)
part A pins: 2 I/O0 (0A2) (io), 3 I/O1 (0A3) (io), 4 I/O2 (0A4) (io), 5 I/O3 (0A7) (io), 6 I/O4 (0A8) (io), 7 I/O5 (0A11) (io), 8 I/O6 (0A12) (io), 9 I/O7 (0A13) (io), 11 I/O8 (0D13) (io), 12 I/O9 (0D12) (io), 13 I/O10 (0D11) (io), 14 I/O11 (0D8) (io), 15 I/O12 (0D7) (io), 16 I/O13 (0D4) (io), 17 I/O14 (0D3) (io), 18 I/O15 (0D2) (io), 23 I/O16 (1D2) (io), 24 I/O17 (1D3) (io), 25 I/O18 (1D4) (io), 26 I/O19 (1D7) (io), 27 I/O20 (1D8) (io), 28 I/O21 (1D11) (io), 29 I/O22 (1D12) (io), 30 I/O23 (1D13) (io), 32 I/O24 (1A15) (io), 33 I/O25 (1A14) (io), 34 I/O26 (1A13) (io), 35 I/O27 (1A12) (io), 36 I/O28 (1A11) (io), 37 I/O29 (1A10) (io), 38 I/O30 (1A9) (io), 39 I/O31 (1A8) (io), 43 I/O32 (1A7) (io), 44 I/O33 (1A6) (io), 45 I/O34 (1A5) (io), 46 I/O35 (1A4) (io), 47 I/O36 (1A3) (io), 48 I/O37 (1A2) (io), 49 I/O38 (1A1) (io), 50 I/O39 (1A0) (io), 53 I/O40 (1B3) (io), 54 I/O41 (1B4) (io), 55 I/O42 (1B7) (io), 56 I/O43 (1B8) (io), 57 I/O44 (1B11) (io), 58 I/O45 (1B12) (io), 63 I/O46 (2B12) (io), 64 I/O47 (2B11) (io), 65 I/O48 (2B8) (io), 66 I/O49 (2B7) (io), 67 I/O50 (2B4) (io), 68 I/O51 (2B3) (io), 71 I/O52 (2A0) (io), 72 I/O53 (2A1) (io), 73 I/O54 (2A2) (io), 74 I/O55 (2A3) (io), 75 I/O56 (2A4) (io), 76 I/O57 (2A5) (io), 77 I/O58 (2A6) (io), 78 I/O59 (2A7) (io), 82 I/O60 (2A8) (io), 83 I/O61 (2A9) (io), 84 I/O62 (2A10) (io), 85 I/O63 (2A11) (io), 86 I/O64 (2A12) (io), 87 I/O65 (2A13) (io), 88 I/O66 (2A14) (io), 89 I/O67 (2A15) (io), 91 I/O68 (2D13) (io), 92 I/O69 (2D12) (io), 93 I/O70 (2D11) (io), 94 I/O71 (2D8) (io), 95 I/O72 (2D7) (io), 96 I/O73 (2D4) (io), 97 I/O74 (2D3) (io), 98 I/O75 (2D2) (io), 103 I/O76 (3D2) (io), 104 I/O77 (3D3) (io), 105 I/O78 (3D4) (io), 106 I/O79 (3D7) (io), 107 I/O80 (3D8) (io), 108 I/O81 (3D11) (io), 109 I/O82 (3D12) (io), 110 I/O83 (3D13) (io), 112 I/O84 (3A13) (io), 113 I/O85 (3A12) (io), 114 I/O86 (3A11) (io), 115 I/O87 (3A8) (io), 116 I/O88 (3A7) (io), 117 I/O89 (3A4) (io), 118 I/O90 (3A3) (io), 119 I/O91 (3A2) (io), 123 I/O92 (3B2) (io), 124 I/O93 (3B3) (io), 125 I/O94 (3B4) (io), 126 I/O95 (3B7) (io), 127 I/O96 (3B8) (io), 128 I/O97 (3B11) (io), 129 I/O98 (3B12) (io), 130 I/O99 (3B13) (io), 133 I/O100 (4B12) (io), 134 I/O101 (4B11) (io), 135 I/O102 (4B8) (io), 136 I/O103 (4B7) (io), 137 I/O104 (4B4) (io), 138 I/O105 (4B3) (io), 143 I/O106 (4A3) (io), 144 I/O107 (4A4) (io), 145 I/O108 (4A7) (io), 146 I/O109 (4A8) (io), 147 I/O110 (4A11) (io), 148 I/O111 (4A12) (io), 151 I/O112 (0B13) (io), 152 I/O113 (0B12) (io), 153 I/O114 (0B11) (io), 154 I/O115 (0B8) (io), 155 I/O116 (0B7) (io), 156 I/O117 (0B4) (io), 157 I/O118 (0B3) (io), 158 I/O119 (0B2) (io)
part B pins: 1 TDI (in), 10 GND (power), 19 I0/CLK0 (in), 20 VCC (power), 21 GND (power), 22 I1/CLK1 (in), 31 GND (power), 40 TCK (in), 41 GND (power), 42 VCC (power), 51 GND (power), 52 VCC (power), 59 VCC (power), 60 GND (power), 61 GND (power), 62 VCC (power), 69 VCC (power), 70 GND (power), 79 VCC (power), 80 GND (power), 81 TMS (in), 90 GND (power), 99 I2/CLK2 (in), 100 VCC (power), 101 GND (power), 102 I3/CLK3 (in), 111 GND (power), 120 TDO (out), 121 GND (power), 122 VCC (power), 131 GND (power), 132 VCC (power), 139 VCC (power), 140 GND (power), 141 GND (power), 142 VCC (power), 149 VCC (power), 150 GND (power), 159 VCC (power), 160 GND (power)

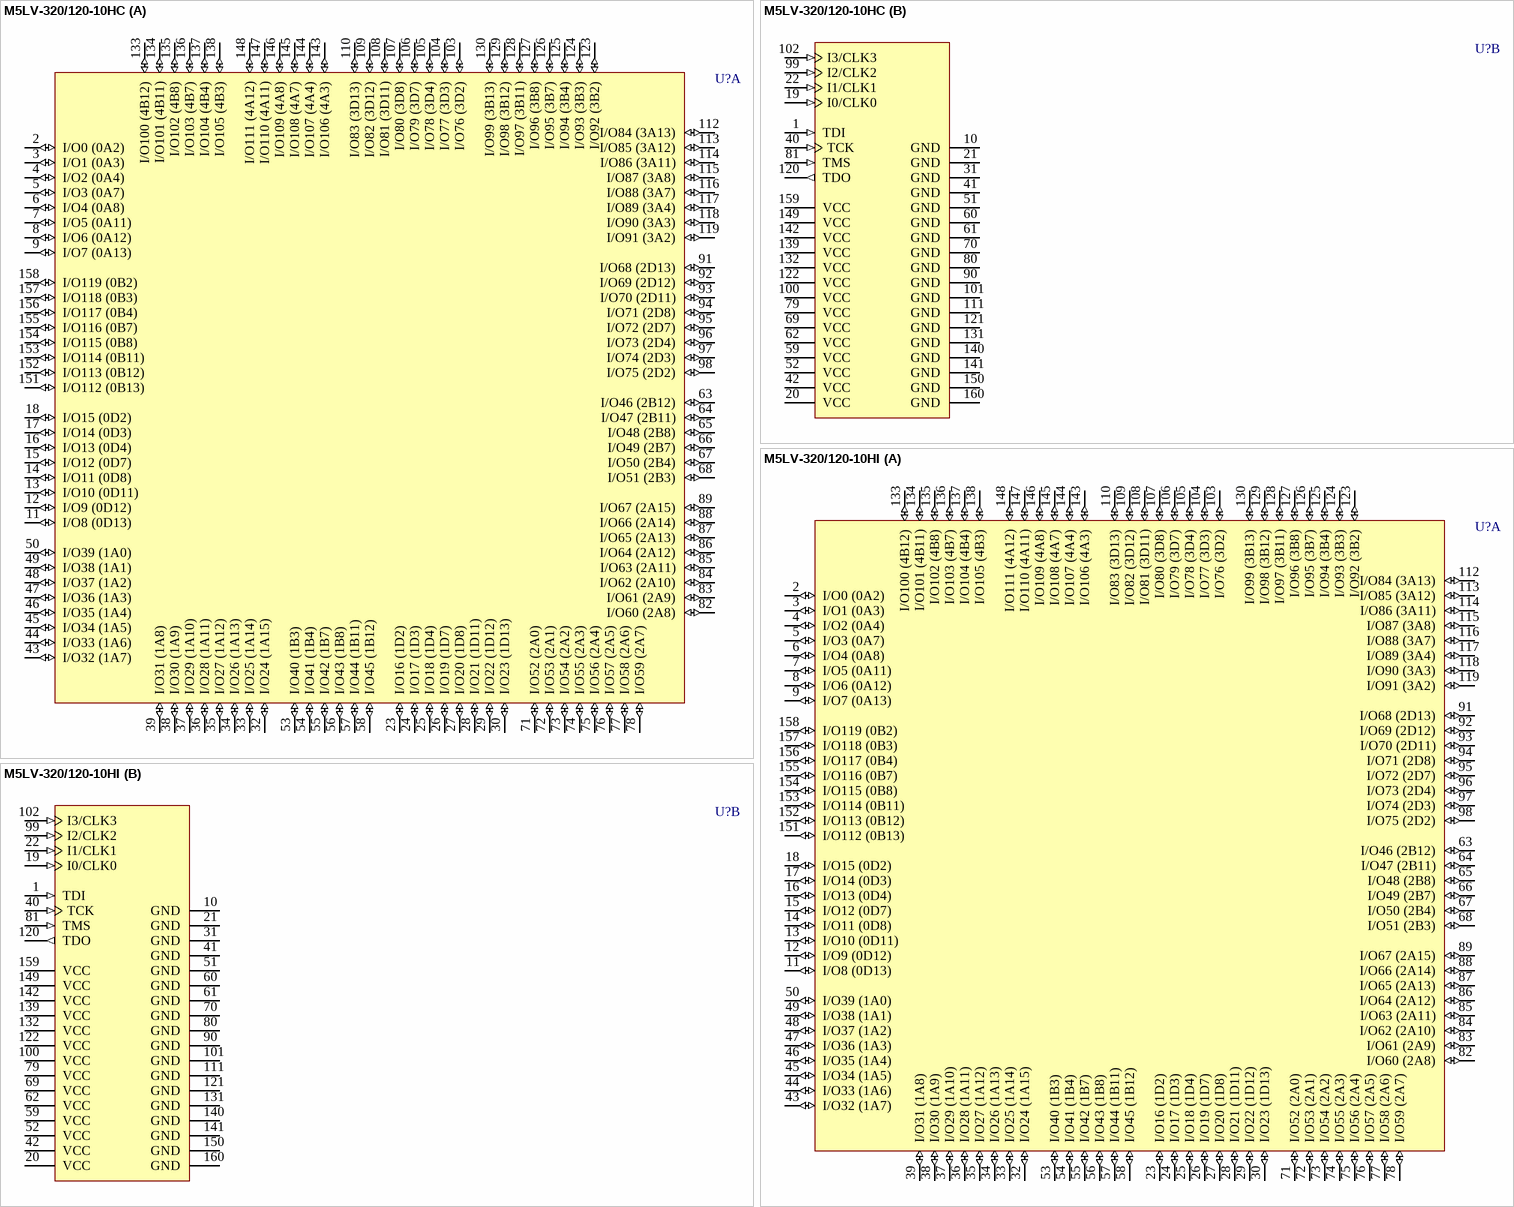
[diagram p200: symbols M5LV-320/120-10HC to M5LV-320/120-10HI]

## M5LV-320/120-10HC
designator U?
High-Density and High-I/O Complex PLD
footprint MQFP160_N (QFP, 160-Leads, Body 27.7 x 27.7mm, Pitch 0.65mm, IPC Medium Density)
footprint MQFP160_L (QFP, 160-Leads, Body 27.7 x 27.7mm, Pitch 0.65mm, IPC High Density)
footprint MQFP160_M (QFP, 160-Leads, Body 27.7 x 27.7mm, Pitch 0.65mm, IPC Low Density)
3D model M5LV-MQFP160 (160-Pin Quad Flat Pack 0.65 mm Pitch)
part A pins: 2 I/O0 (0A2) (io), 3 I/O1 (0A3) (io), 4 I/O2 (0A4) (io), 5 I/O3 (0A7) (io), 6 I/O4 (0A8) (io), 7 I/O5 (0A11) (io), 8 I/O6 (0A12) (io), 9 I/O7 (0A13) (io), 11 I/O8 (0D13) (io), 12 I/O9 (0D12) (io), 13 I/O10 (0D11) (io), 14 I/O11 (0D8) (io), 15 I/O12 (0D7) (io), 16 I/O13 (0D4) (io), 17 I/O14 (0D3) (io), 18 I/O15 (0D2) (io), 23 I/O16 (1D2) (io), 24 I/O17 (1D3) (io), 25 I/O18 (1D4) (io), 26 I/O19 (1D7) (io), 27 I/O20 (1D8) (io), 28 I/O21 (1D11) (io), 29 I/O22 (1D12) (io), 30 I/O23 (1D13) (io), 32 I/O24 (1A15) (io), 33 I/O25 (1A14) (io), 34 I/O26 (1A13) (io), 35 I/O27 (1A12) (io), 36 I/O28 (1A11) (io), 37 I/O29 (1A10) (io), 38 I/O30 (1A9) (io), 39 I/O31 (1A8) (io), 43 I/O32 (1A7) (io), 44 I/O33 (1A6) (io), 45 I/O34 (1A5) (io), 46 I/O35 (1A4) (io), 47 I/O36 (1A3) (io), 48 I/O37 (1A2) (io), 49 I/O38 (1A1) (io), 50 I/O39 (1A0) (io), 53 I/O40 (1B3) (io), 54 I/O41 (1B4) (io), 55 I/O42 (1B7) (io), 56 I/O43 (1B8) (io), 57 I/O44 (1B11) (io), 58 I/O45 (1B12) (io), 63 I/O46 (2B12) (io), 64 I/O47 (2B11) (io), 65 I/O48 (2B8) (io), 66 I/O49 (2B7) (io), 67 I/O50 (2B4) (io), 68 I/O51 (2B3) (io), 71 I/O52 (2A0) (io), 72 I/O53 (2A1) (io), 73 I/O54 (2A2) (io), 74 I/O55 (2A3) (io), 75 I/O56 (2A4) (io), 76 I/O57 (2A5) (io), 77 I/O58 (2A6) (io), 78 I/O59 (2A7) (io), 82 I/O60 (2A8) (io), 83 I/O61 (2A9) (io), 84 I/O62 (2A10) (io), 85 I/O63 (2A11) (io), 86 I/O64 (2A12) (io), 87 I/O65 (2A13) (io), 88 I/O66 (2A14) (io), 89 I/O67 (2A15) (io), 91 I/O68 (2D13) (io), 92 I/O69 (2D12) (io), 93 I/O70 (2D11) (io), 94 I/O71 (2D8) (io), 95 I/O72 (2D7) (io), 96 I/O73 (2D4) (io), 97 I/O74 (2D3) (io), 98 I/O75 (2D2) (io), 103 I/O76 (3D2) (io), 104 I/O77 (3D3) (io), 105 I/O78 (3D4) (io), 106 I/O79 (3D7) (io), 107 I/O80 (3D8) (io), 108 I/O81 (3D11) (io), 109 I/O82 (3D12) (io), 110 I/O83 (3D13) (io), 112 I/O84 (3A13) (io), 113 I/O85 (3A12) (io), 114 I/O86 (3A11) (io), 115 I/O87 (3A8) (io), 116 I/O88 (3A7) (io), 117 I/O89 (3A4) (io), 118 I/O90 (3A3) (io), 119 I/O91 (3A2) (io), 123 I/O92 (3B2) (io), 124 I/O93 (3B3) (io), 125 I/O94 (3B4) (io), 126 I/O95 (3B7) (io), 127 I/O96 (3B8) (io), 128 I/O97 (3B11) (io), 129 I/O98 (3B12) (io), 130 I/O99 (3B13) (io), 133 I/O100 (4B12) (io), 134 I/O101 (4B11) (io), 135 I/O102 (4B8) (io), 136 I/O103 (4B7) (io), 137 I/O104 (4B4) (io), 138 I/O105 (4B3) (io), 143 I/O106 (4A3) (io), 144 I/O107 (4A4) (io), 145 I/O108 (4A7) (io), 146 I/O109 (4A8) (io), 147 I/O110 (4A11) (io), 148 I/O111 (4A12) (io), 151 I/O112 (0B13) (io), 152 I/O113 (0B12) (io), 153 I/O114 (0B11) (io), 154 I/O115 (0B8) (io), 155 I/O116 (0B7) (io), 156 I/O117 (0B4) (io), 157 I/O118 (0B3) (io), 158 I/O119 (0B2) (io)
part B pins: 1 TDI (in), 10 GND (power), 19 I0/CLK0 (in), 20 VCC (power), 21 GND (power), 22 I1/CLK1 (in), 31 GND (power), 40 TCK (in), 41 GND (power), 42 VCC (power), 51 GND (power), 52 VCC (power), 59 VCC (power), 60 GND (power), 61 GND (power), 62 VCC (power), 69 VCC (power), 70 GND (power), 79 VCC (power), 80 GND (power), 81 TMS (in), 90 GND (power), 99 I2/CLK2 (in), 100 VCC (power), 101 GND (power), 102 I3/CLK3 (in), 111 GND (power), 120 TDO (out), 121 GND (power), 122 VCC (power), 131 GND (power), 132 VCC (power), 139 VCC (power), 140 GND (power), 141 GND (power), 142 VCC (power), 149 VCC (power), 150 GND (power), 159 VCC (power), 160 GND (power)

## M5LV-320/120-10HI
designator U?
High-Density and High-I/O Complex PLD
footprint MQFP160_N (QFP, 160-Leads, Body 27.7 x 27.7mm, Pitch 0.65mm, IPC Medium Density)
footprint MQFP160_L (QFP, 160-Leads, Body 27.7 x 27.7mm, Pitch 0.65mm, IPC High Density)
footprint MQFP160_M (QFP, 160-Leads, Body 27.7 x 27.7mm, Pitch 0.65mm, IPC Low Density)
3D model M5LV-MQFP160 (160-Pin Quad Flat Pack 0.65 mm Pitch)
part A pins: 2 I/O0 (0A2) (io), 3 I/O1 (0A3) (io), 4 I/O2 (0A4) (io), 5 I/O3 (0A7) (io), 6 I/O4 (0A8) (io), 7 I/O5 (0A11) (io), 8 I/O6 (0A12) (io), 9 I/O7 (0A13) (io), 11 I/O8 (0D13) (io), 12 I/O9 (0D12) (io), 13 I/O10 (0D11) (io), 14 I/O11 (0D8) (io), 15 I/O12 (0D7) (io), 16 I/O13 (0D4) (io), 17 I/O14 (0D3) (io), 18 I/O15 (0D2) (io), 23 I/O16 (1D2) (io), 24 I/O17 (1D3) (io), 25 I/O18 (1D4) (io), 26 I/O19 (1D7) (io), 27 I/O20 (1D8) (io), 28 I/O21 (1D11) (io), 29 I/O22 (1D12) (io), 30 I/O23 (1D13) (io), 32 I/O24 (1A15) (io), 33 I/O25 (1A14) (io), 34 I/O26 (1A13) (io), 35 I/O27 (1A12) (io), 36 I/O28 (1A11) (io), 37 I/O29 (1A10) (io), 38 I/O30 (1A9) (io), 39 I/O31 (1A8) (io), 43 I/O32 (1A7) (io), 44 I/O33 (1A6) (io), 45 I/O34 (1A5) (io), 46 I/O35 (1A4) (io), 47 I/O36 (1A3) (io), 48 I/O37 (1A2) (io), 49 I/O38 (1A1) (io), 50 I/O39 (1A0) (io), 53 I/O40 (1B3) (io), 54 I/O41 (1B4) (io), 55 I/O42 (1B7) (io), 56 I/O43 (1B8) (io), 57 I/O44 (1B11) (io), 58 I/O45 (1B12) (io), 63 I/O46 (2B12) (io), 64 I/O47 (2B11) (io), 65 I/O48 (2B8) (io), 66 I/O49 (2B7) (io), 67 I/O50 (2B4) (io), 68 I/O51 (2B3) (io), 71 I/O52 (2A0) (io), 72 I/O53 (2A1) (io), 73 I/O54 (2A2) (io), 74 I/O55 (2A3) (io), 75 I/O56 (2A4) (io), 76 I/O57 (2A5) (io), 77 I/O58 (2A6) (io), 78 I/O59 (2A7) (io), 82 I/O60 (2A8) (io), 83 I/O61 (2A9) (io), 84 I/O62 (2A10) (io), 85 I/O63 (2A11) (io), 86 I/O64 (2A12) (io), 87 I/O65 (2A13) (io), 88 I/O66 (2A14) (io), 89 I/O67 (2A15) (io), 91 I/O68 (2D13) (io), 92 I/O69 (2D12) (io), 93 I/O70 (2D11) (io), 94 I/O71 (2D8) (io), 95 I/O72 (2D7) (io), 96 I/O73 (2D4) (io), 97 I/O74 (2D3) (io), 98 I/O75 (2D2) (io), 103 I/O76 (3D2) (io), 104 I/O77 (3D3) (io), 105 I/O78 (3D4) (io), 106 I/O79 (3D7) (io), 107 I/O80 (3D8) (io), 108 I/O81 (3D11) (io), 109 I/O82 (3D12) (io), 110 I/O83 (3D13) (io), 112 I/O84 (3A13) (io), 113 I/O85 (3A12) (io), 114 I/O86 (3A11) (io), 115 I/O87 (3A8) (io), 116 I/O88 (3A7) (io), 117 I/O89 (3A4) (io), 118 I/O90 (3A3) (io), 119 I/O91 (3A2) (io), 123 I/O92 (3B2) (io), 124 I/O93 (3B3) (io), 125 I/O94 (3B4) (io), 126 I/O95 (3B7) (io), 127 I/O96 (3B8) (io), 128 I/O97 (3B11) (io), 129 I/O98 (3B12) (io), 130 I/O99 (3B13) (io), 133 I/O100 (4B12) (io), 134 I/O101 (4B11) (io), 135 I/O102 (4B8) (io), 136 I/O103 (4B7) (io), 137 I/O104 (4B4) (io), 138 I/O105 (4B3) (io), 143 I/O106 (4A3) (io), 144 I/O107 (4A4) (io), 145 I/O108 (4A7) (io), 146 I/O109 (4A8) (io), 147 I/O110 (4A11) (io), 148 I/O111 (4A12) (io), 151 I/O112 (0B13) (io), 152 I/O113 (0B12) (io), 153 I/O114 (0B11) (io), 154 I/O115 (0B8) (io), 155 I/O116 (0B7) (io), 156 I/O117 (0B4) (io), 157 I/O118 (0B3) (io), 158 I/O119 (0B2) (io)
part B pins: 1 TDI (in), 10 GND (power), 19 I0/CLK0 (in), 20 VCC (power), 21 GND (power), 22 I1/CLK1 (in), 31 GND (power), 40 TCK (in), 41 GND (power), 42 VCC (power), 51 GND (power), 52 VCC (power), 59 VCC (power), 60 GND (power), 61 GND (power), 62 VCC (power), 69 VCC (power), 70 GND (power), 79 VCC (power), 80 GND (power), 81 TMS (in), 90 GND (power), 99 I2/CLK2 (in), 100 VCC (power), 101 GND (power), 102 I3/CLK3 (in), 111 GND (power), 120 TDO (out), 121 GND (power), 122 VCC (power), 131 GND (power), 132 VCC (power), 139 VCC (power), 140 GND (power), 141 GND (power), 142 VCC (power), 149 VCC (power), 150 GND (power), 159 VCC (power), 160 GND (power)

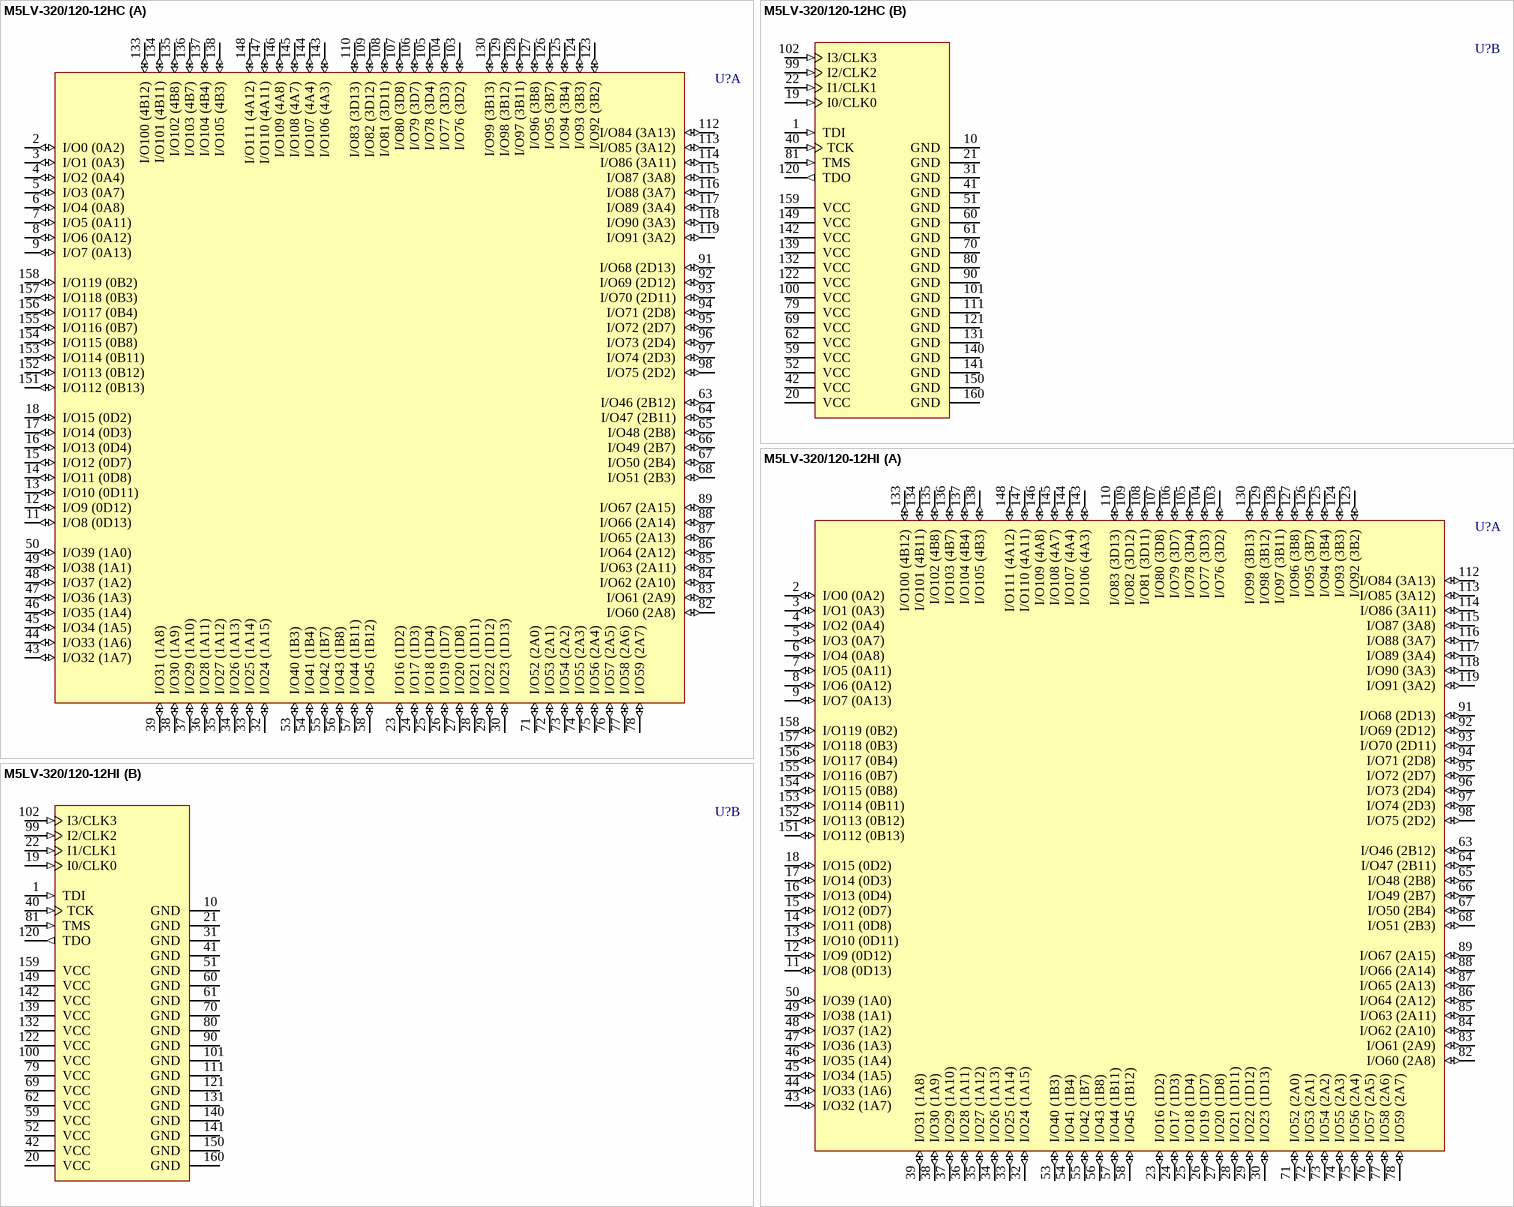
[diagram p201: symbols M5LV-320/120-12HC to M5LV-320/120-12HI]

## M5LV-320/120-12HC
designator U?
High-Density and High-I/O Complex PLD
footprint MQFP160_N (QFP, 160-Leads, Body 27.7 x 27.7mm, Pitch 0.65mm, IPC Medium Density)
footprint MQFP160_L (QFP, 160-Leads, Body 27.7 x 27.7mm, Pitch 0.65mm, IPC High Density)
footprint MQFP160_M (QFP, 160-Leads, Body 27.7 x 27.7mm, Pitch 0.65mm, IPC Low Density)
3D model M5LV-MQFP160 (160-Pin Quad Flat Pack 0.65 mm Pitch)
part A pins: 2 I/O0 (0A2) (io), 3 I/O1 (0A3) (io), 4 I/O2 (0A4) (io), 5 I/O3 (0A7) (io), 6 I/O4 (0A8) (io), 7 I/O5 (0A11) (io), 8 I/O6 (0A12) (io), 9 I/O7 (0A13) (io), 11 I/O8 (0D13) (io), 12 I/O9 (0D12) (io), 13 I/O10 (0D11) (io), 14 I/O11 (0D8) (io), 15 I/O12 (0D7) (io), 16 I/O13 (0D4) (io), 17 I/O14 (0D3) (io), 18 I/O15 (0D2) (io), 23 I/O16 (1D2) (io), 24 I/O17 (1D3) (io), 25 I/O18 (1D4) (io), 26 I/O19 (1D7) (io), 27 I/O20 (1D8) (io), 28 I/O21 (1D11) (io), 29 I/O22 (1D12) (io), 30 I/O23 (1D13) (io), 32 I/O24 (1A15) (io), 33 I/O25 (1A14) (io), 34 I/O26 (1A13) (io), 35 I/O27 (1A12) (io), 36 I/O28 (1A11) (io), 37 I/O29 (1A10) (io), 38 I/O30 (1A9) (io), 39 I/O31 (1A8) (io), 43 I/O32 (1A7) (io), 44 I/O33 (1A6) (io), 45 I/O34 (1A5) (io), 46 I/O35 (1A4) (io), 47 I/O36 (1A3) (io), 48 I/O37 (1A2) (io), 49 I/O38 (1A1) (io), 50 I/O39 (1A0) (io), 53 I/O40 (1B3) (io), 54 I/O41 (1B4) (io), 55 I/O42 (1B7) (io), 56 I/O43 (1B8) (io), 57 I/O44 (1B11) (io), 58 I/O45 (1B12) (io), 63 I/O46 (2B12) (io), 64 I/O47 (2B11) (io), 65 I/O48 (2B8) (io), 66 I/O49 (2B7) (io), 67 I/O50 (2B4) (io), 68 I/O51 (2B3) (io), 71 I/O52 (2A0) (io), 72 I/O53 (2A1) (io), 73 I/O54 (2A2) (io), 74 I/O55 (2A3) (io), 75 I/O56 (2A4) (io), 76 I/O57 (2A5) (io), 77 I/O58 (2A6) (io), 78 I/O59 (2A7) (io), 82 I/O60 (2A8) (io), 83 I/O61 (2A9) (io), 84 I/O62 (2A10) (io), 85 I/O63 (2A11) (io), 86 I/O64 (2A12) (io), 87 I/O65 (2A13) (io), 88 I/O66 (2A14) (io), 89 I/O67 (2A15) (io), 91 I/O68 (2D13) (io), 92 I/O69 (2D12) (io), 93 I/O70 (2D11) (io), 94 I/O71 (2D8) (io), 95 I/O72 (2D7) (io), 96 I/O73 (2D4) (io), 97 I/O74 (2D3) (io), 98 I/O75 (2D2) (io), 103 I/O76 (3D2) (io), 104 I/O77 (3D3) (io), 105 I/O78 (3D4) (io), 106 I/O79 (3D7) (io), 107 I/O80 (3D8) (io), 108 I/O81 (3D11) (io), 109 I/O82 (3D12) (io), 110 I/O83 (3D13) (io), 112 I/O84 (3A13) (io), 113 I/O85 (3A12) (io), 114 I/O86 (3A11) (io), 115 I/O87 (3A8) (io), 116 I/O88 (3A7) (io), 117 I/O89 (3A4) (io), 118 I/O90 (3A3) (io), 119 I/O91 (3A2) (io), 123 I/O92 (3B2) (io), 124 I/O93 (3B3) (io), 125 I/O94 (3B4) (io), 126 I/O95 (3B7) (io), 127 I/O96 (3B8) (io), 128 I/O97 (3B11) (io), 129 I/O98 (3B12) (io), 130 I/O99 (3B13) (io), 133 I/O100 (4B12) (io), 134 I/O101 (4B11) (io), 135 I/O102 (4B8) (io), 136 I/O103 (4B7) (io), 137 I/O104 (4B4) (io), 138 I/O105 (4B3) (io), 143 I/O106 (4A3) (io), 144 I/O107 (4A4) (io), 145 I/O108 (4A7) (io), 146 I/O109 (4A8) (io), 147 I/O110 (4A11) (io), 148 I/O111 (4A12) (io), 151 I/O112 (0B13) (io), 152 I/O113 (0B12) (io), 153 I/O114 (0B11) (io), 154 I/O115 (0B8) (io), 155 I/O116 (0B7) (io), 156 I/O117 (0B4) (io), 157 I/O118 (0B3) (io), 158 I/O119 (0B2) (io)
part B pins: 1 TDI (in), 10 GND (power), 19 I0/CLK0 (in), 20 VCC (power), 21 GND (power), 22 I1/CLK1 (in), 31 GND (power), 40 TCK (in), 41 GND (power), 42 VCC (power), 51 GND (power), 52 VCC (power), 59 VCC (power), 60 GND (power), 61 GND (power), 62 VCC (power), 69 VCC (power), 70 GND (power), 79 VCC (power), 80 GND (power), 81 TMS (in), 90 GND (power), 99 I2/CLK2 (in), 100 VCC (power), 101 GND (power), 102 I3/CLK3 (in), 111 GND (power), 120 TDO (out), 121 GND (power), 122 VCC (power), 131 GND (power), 132 VCC (power), 139 VCC (power), 140 GND (power), 141 GND (power), 142 VCC (power), 149 VCC (power), 150 GND (power), 159 VCC (power), 160 GND (power)

## M5LV-320/120-12HI
designator U?
High-Density and High-I/O Complex PLD
footprint MQFP160_N (QFP, 160-Leads, Body 27.7 x 27.7mm, Pitch 0.65mm, IPC Medium Density)
footprint MQFP160_L (QFP, 160-Leads, Body 27.7 x 27.7mm, Pitch 0.65mm, IPC High Density)
footprint MQFP160_M (QFP, 160-Leads, Body 27.7 x 27.7mm, Pitch 0.65mm, IPC Low Density)
3D model M5LV-MQFP160 (160-Pin Quad Flat Pack 0.65 mm Pitch)
part A pins: 2 I/O0 (0A2) (io), 3 I/O1 (0A3) (io), 4 I/O2 (0A4) (io), 5 I/O3 (0A7) (io), 6 I/O4 (0A8) (io), 7 I/O5 (0A11) (io), 8 I/O6 (0A12) (io), 9 I/O7 (0A13) (io), 11 I/O8 (0D13) (io), 12 I/O9 (0D12) (io), 13 I/O10 (0D11) (io), 14 I/O11 (0D8) (io), 15 I/O12 (0D7) (io), 16 I/O13 (0D4) (io), 17 I/O14 (0D3) (io), 18 I/O15 (0D2) (io), 23 I/O16 (1D2) (io), 24 I/O17 (1D3) (io), 25 I/O18 (1D4) (io), 26 I/O19 (1D7) (io), 27 I/O20 (1D8) (io), 28 I/O21 (1D11) (io), 29 I/O22 (1D12) (io), 30 I/O23 (1D13) (io), 32 I/O24 (1A15) (io), 33 I/O25 (1A14) (io), 34 I/O26 (1A13) (io), 35 I/O27 (1A12) (io), 36 I/O28 (1A11) (io), 37 I/O29 (1A10) (io), 38 I/O30 (1A9) (io), 39 I/O31 (1A8) (io), 43 I/O32 (1A7) (io), 44 I/O33 (1A6) (io), 45 I/O34 (1A5) (io), 46 I/O35 (1A4) (io), 47 I/O36 (1A3) (io), 48 I/O37 (1A2) (io), 49 I/O38 (1A1) (io), 50 I/O39 (1A0) (io), 53 I/O40 (1B3) (io), 54 I/O41 (1B4) (io), 55 I/O42 (1B7) (io), 56 I/O43 (1B8) (io), 57 I/O44 (1B11) (io), 58 I/O45 (1B12) (io), 63 I/O46 (2B12) (io), 64 I/O47 (2B11) (io), 65 I/O48 (2B8) (io), 66 I/O49 (2B7) (io), 67 I/O50 (2B4) (io), 68 I/O51 (2B3) (io), 71 I/O52 (2A0) (io), 72 I/O53 (2A1) (io), 73 I/O54 (2A2) (io), 74 I/O55 (2A3) (io), 75 I/O56 (2A4) (io), 76 I/O57 (2A5) (io), 77 I/O58 (2A6) (io), 78 I/O59 (2A7) (io), 82 I/O60 (2A8) (io), 83 I/O61 (2A9) (io), 84 I/O62 (2A10) (io), 85 I/O63 (2A11) (io), 86 I/O64 (2A12) (io), 87 I/O65 (2A13) (io), 88 I/O66 (2A14) (io), 89 I/O67 (2A15) (io), 91 I/O68 (2D13) (io), 92 I/O69 (2D12) (io), 93 I/O70 (2D11) (io), 94 I/O71 (2D8) (io), 95 I/O72 (2D7) (io), 96 I/O73 (2D4) (io), 97 I/O74 (2D3) (io), 98 I/O75 (2D2) (io), 103 I/O76 (3D2) (io), 104 I/O77 (3D3) (io), 105 I/O78 (3D4) (io), 106 I/O79 (3D7) (io), 107 I/O80 (3D8) (io), 108 I/O81 (3D11) (io), 109 I/O82 (3D12) (io), 110 I/O83 (3D13) (io), 112 I/O84 (3A13) (io), 113 I/O85 (3A12) (io), 114 I/O86 (3A11) (io), 115 I/O87 (3A8) (io), 116 I/O88 (3A7) (io), 117 I/O89 (3A4) (io), 118 I/O90 (3A3) (io), 119 I/O91 (3A2) (io), 123 I/O92 (3B2) (io), 124 I/O93 (3B3) (io), 125 I/O94 (3B4) (io), 126 I/O95 (3B7) (io), 127 I/O96 (3B8) (io), 128 I/O97 (3B11) (io), 129 I/O98 (3B12) (io), 130 I/O99 (3B13) (io), 133 I/O100 (4B12) (io), 134 I/O101 (4B11) (io), 135 I/O102 (4B8) (io), 136 I/O103 (4B7) (io), 137 I/O104 (4B4) (io), 138 I/O105 (4B3) (io), 143 I/O106 (4A3) (io), 144 I/O107 (4A4) (io), 145 I/O108 (4A7) (io), 146 I/O109 (4A8) (io), 147 I/O110 (4A11) (io), 148 I/O111 (4A12) (io), 151 I/O112 (0B13) (io), 152 I/O113 (0B12) (io), 153 I/O114 (0B11) (io), 154 I/O115 (0B8) (io), 155 I/O116 (0B7) (io), 156 I/O117 (0B4) (io), 157 I/O118 (0B3) (io), 158 I/O119 (0B2) (io)
part B pins: 1 TDI (in), 10 GND (power), 19 I0/CLK0 (in), 20 VCC (power), 21 GND (power), 22 I1/CLK1 (in), 31 GND (power), 40 TCK (in), 41 GND (power), 42 VCC (power), 51 GND (power), 52 VCC (power), 59 VCC (power), 60 GND (power), 61 GND (power), 62 VCC (power), 69 VCC (power), 70 GND (power), 79 VCC (power), 80 GND (power), 81 TMS (in), 90 GND (power), 99 I2/CLK2 (in), 100 VCC (power), 101 GND (power), 102 I3/CLK3 (in), 111 GND (power), 120 TDO (out), 121 GND (power), 122 VCC (power), 131 GND (power), 132 VCC (power), 139 VCC (power), 140 GND (power), 141 GND (power), 142 VCC (power), 149 VCC (power), 150 GND (power), 159 VCC (power), 160 GND (power)

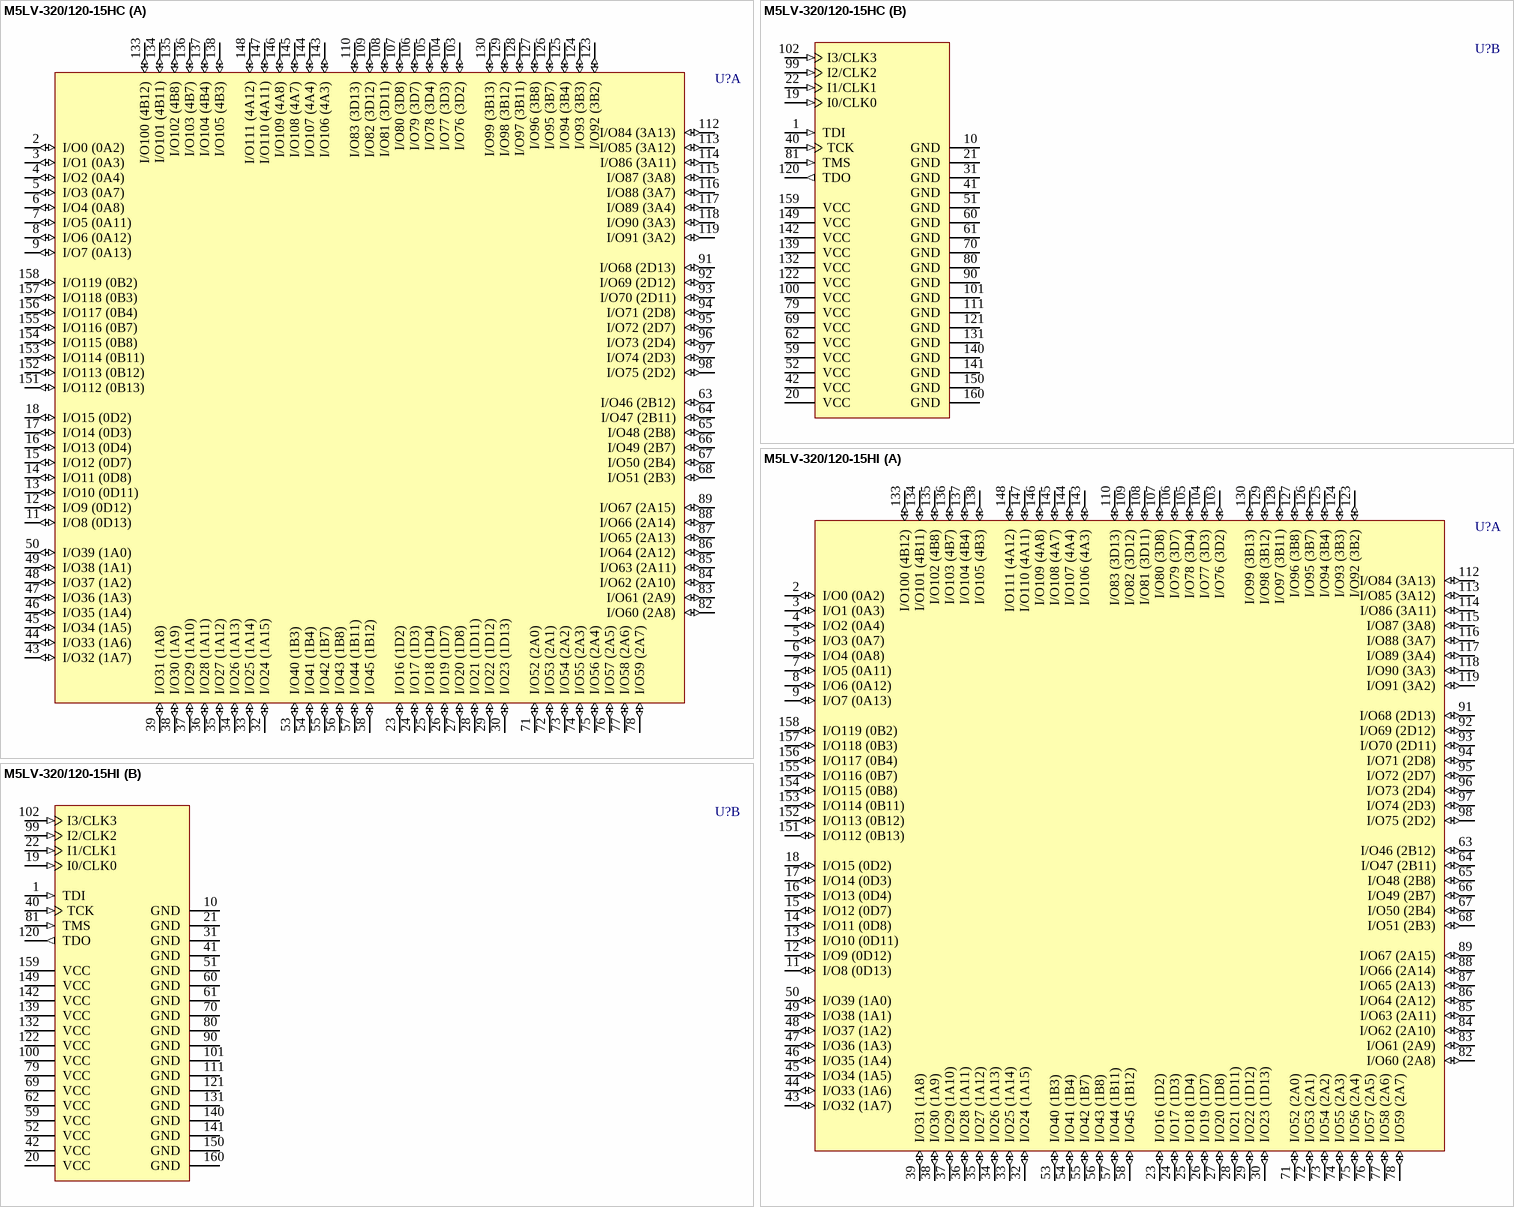
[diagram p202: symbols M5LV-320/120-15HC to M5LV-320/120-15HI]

## M5LV-320/120-15HC
designator U?
High-Density and High-I/O Complex PLD
footprint MQFP160_N (QFP, 160-Leads, Body 27.7 x 27.7mm, Pitch 0.65mm, IPC Medium Density)
footprint MQFP160_L (QFP, 160-Leads, Body 27.7 x 27.7mm, Pitch 0.65mm, IPC High Density)
footprint MQFP160_M (QFP, 160-Leads, Body 27.7 x 27.7mm, Pitch 0.65mm, IPC Low Density)
3D model M5LV-MQFP160 (160-Pin Quad Flat Pack 0.65 mm Pitch)
part A pins: 2 I/O0 (0A2) (io), 3 I/O1 (0A3) (io), 4 I/O2 (0A4) (io), 5 I/O3 (0A7) (io), 6 I/O4 (0A8) (io), 7 I/O5 (0A11) (io), 8 I/O6 (0A12) (io), 9 I/O7 (0A13) (io), 11 I/O8 (0D13) (io), 12 I/O9 (0D12) (io), 13 I/O10 (0D11) (io), 14 I/O11 (0D8) (io), 15 I/O12 (0D7) (io), 16 I/O13 (0D4) (io), 17 I/O14 (0D3) (io), 18 I/O15 (0D2) (io), 23 I/O16 (1D2) (io), 24 I/O17 (1D3) (io), 25 I/O18 (1D4) (io), 26 I/O19 (1D7) (io), 27 I/O20 (1D8) (io), 28 I/O21 (1D11) (io), 29 I/O22 (1D12) (io), 30 I/O23 (1D13) (io), 32 I/O24 (1A15) (io), 33 I/O25 (1A14) (io), 34 I/O26 (1A13) (io), 35 I/O27 (1A12) (io), 36 I/O28 (1A11) (io), 37 I/O29 (1A10) (io), 38 I/O30 (1A9) (io), 39 I/O31 (1A8) (io), 43 I/O32 (1A7) (io), 44 I/O33 (1A6) (io), 45 I/O34 (1A5) (io), 46 I/O35 (1A4) (io), 47 I/O36 (1A3) (io), 48 I/O37 (1A2) (io), 49 I/O38 (1A1) (io), 50 I/O39 (1A0) (io), 53 I/O40 (1B3) (io), 54 I/O41 (1B4) (io), 55 I/O42 (1B7) (io), 56 I/O43 (1B8) (io), 57 I/O44 (1B11) (io), 58 I/O45 (1B12) (io), 63 I/O46 (2B12) (io), 64 I/O47 (2B11) (io), 65 I/O48 (2B8) (io), 66 I/O49 (2B7) (io), 67 I/O50 (2B4) (io), 68 I/O51 (2B3) (io), 71 I/O52 (2A0) (io), 72 I/O53 (2A1) (io), 73 I/O54 (2A2) (io), 74 I/O55 (2A3) (io), 75 I/O56 (2A4) (io), 76 I/O57 (2A5) (io), 77 I/O58 (2A6) (io), 78 I/O59 (2A7) (io), 82 I/O60 (2A8) (io), 83 I/O61 (2A9) (io), 84 I/O62 (2A10) (io), 85 I/O63 (2A11) (io), 86 I/O64 (2A12) (io), 87 I/O65 (2A13) (io), 88 I/O66 (2A14) (io), 89 I/O67 (2A15) (io), 91 I/O68 (2D13) (io), 92 I/O69 (2D12) (io), 93 I/O70 (2D11) (io), 94 I/O71 (2D8) (io), 95 I/O72 (2D7) (io), 96 I/O73 (2D4) (io), 97 I/O74 (2D3) (io), 98 I/O75 (2D2) (io), 103 I/O76 (3D2) (io), 104 I/O77 (3D3) (io), 105 I/O78 (3D4) (io), 106 I/O79 (3D7) (io), 107 I/O80 (3D8) (io), 108 I/O81 (3D11) (io), 109 I/O82 (3D12) (io), 110 I/O83 (3D13) (io), 112 I/O84 (3A13) (io), 113 I/O85 (3A12) (io), 114 I/O86 (3A11) (io), 115 I/O87 (3A8) (io), 116 I/O88 (3A7) (io), 117 I/O89 (3A4) (io), 118 I/O90 (3A3) (io), 119 I/O91 (3A2) (io), 123 I/O92 (3B2) (io), 124 I/O93 (3B3) (io), 125 I/O94 (3B4) (io), 126 I/O95 (3B7) (io), 127 I/O96 (3B8) (io), 128 I/O97 (3B11) (io), 129 I/O98 (3B12) (io), 130 I/O99 (3B13) (io), 133 I/O100 (4B12) (io), 134 I/O101 (4B11) (io), 135 I/O102 (4B8) (io), 136 I/O103 (4B7) (io), 137 I/O104 (4B4) (io), 138 I/O105 (4B3) (io), 143 I/O106 (4A3) (io), 144 I/O107 (4A4) (io), 145 I/O108 (4A7) (io), 146 I/O109 (4A8) (io), 147 I/O110 (4A11) (io), 148 I/O111 (4A12) (io), 151 I/O112 (0B13) (io), 152 I/O113 (0B12) (io), 153 I/O114 (0B11) (io), 154 I/O115 (0B8) (io), 155 I/O116 (0B7) (io), 156 I/O117 (0B4) (io), 157 I/O118 (0B3) (io), 158 I/O119 (0B2) (io)
part B pins: 1 TDI (in), 10 GND (power), 19 I0/CLK0 (in), 20 VCC (power), 21 GND (power), 22 I1/CLK1 (in), 31 GND (power), 40 TCK (in), 41 GND (power), 42 VCC (power), 51 GND (power), 52 VCC (power), 59 VCC (power), 60 GND (power), 61 GND (power), 62 VCC (power), 69 VCC (power), 70 GND (power), 79 VCC (power), 80 GND (power), 81 TMS (in), 90 GND (power), 99 I2/CLK2 (in), 100 VCC (power), 101 GND (power), 102 I3/CLK3 (in), 111 GND (power), 120 TDO (out), 121 GND (power), 122 VCC (power), 131 GND (power), 132 VCC (power), 139 VCC (power), 140 GND (power), 141 GND (power), 142 VCC (power), 149 VCC (power), 150 GND (power), 159 VCC (power), 160 GND (power)

## M5LV-320/120-15HI
designator U?
High-Density and High-I/O Complex PLD
footprint MQFP160_N (QFP, 160-Leads, Body 27.7 x 27.7mm, Pitch 0.65mm, IPC Medium Density)
footprint MQFP160_L (QFP, 160-Leads, Body 27.7 x 27.7mm, Pitch 0.65mm, IPC High Density)
footprint MQFP160_M (QFP, 160-Leads, Body 27.7 x 27.7mm, Pitch 0.65mm, IPC Low Density)
3D model M5LV-MQFP160 (160-Pin Quad Flat Pack 0.65 mm Pitch)
part A pins: 2 I/O0 (0A2) (io), 3 I/O1 (0A3) (io), 4 I/O2 (0A4) (io), 5 I/O3 (0A7) (io), 6 I/O4 (0A8) (io), 7 I/O5 (0A11) (io), 8 I/O6 (0A12) (io), 9 I/O7 (0A13) (io), 11 I/O8 (0D13) (io), 12 I/O9 (0D12) (io), 13 I/O10 (0D11) (io), 14 I/O11 (0D8) (io), 15 I/O12 (0D7) (io), 16 I/O13 (0D4) (io), 17 I/O14 (0D3) (io), 18 I/O15 (0D2) (io), 23 I/O16 (1D2) (io), 24 I/O17 (1D3) (io), 25 I/O18 (1D4) (io), 26 I/O19 (1D7) (io), 27 I/O20 (1D8) (io), 28 I/O21 (1D11) (io), 29 I/O22 (1D12) (io), 30 I/O23 (1D13) (io), 32 I/O24 (1A15) (io), 33 I/O25 (1A14) (io), 34 I/O26 (1A13) (io), 35 I/O27 (1A12) (io), 36 I/O28 (1A11) (io), 37 I/O29 (1A10) (io), 38 I/O30 (1A9) (io), 39 I/O31 (1A8) (io), 43 I/O32 (1A7) (io), 44 I/O33 (1A6) (io), 45 I/O34 (1A5) (io), 46 I/O35 (1A4) (io), 47 I/O36 (1A3) (io), 48 I/O37 (1A2) (io), 49 I/O38 (1A1) (io), 50 I/O39 (1A0) (io), 53 I/O40 (1B3) (io), 54 I/O41 (1B4) (io), 55 I/O42 (1B7) (io), 56 I/O43 (1B8) (io), 57 I/O44 (1B11) (io), 58 I/O45 (1B12) (io), 63 I/O46 (2B12) (io), 64 I/O47 (2B11) (io), 65 I/O48 (2B8) (io), 66 I/O49 (2B7) (io), 67 I/O50 (2B4) (io), 68 I/O51 (2B3) (io), 71 I/O52 (2A0) (io), 72 I/O53 (2A1) (io), 73 I/O54 (2A2) (io), 74 I/O55 (2A3) (io), 75 I/O56 (2A4) (io), 76 I/O57 (2A5) (io), 77 I/O58 (2A6) (io), 78 I/O59 (2A7) (io), 82 I/O60 (2A8) (io), 83 I/O61 (2A9) (io), 84 I/O62 (2A10) (io), 85 I/O63 (2A11) (io), 86 I/O64 (2A12) (io), 87 I/O65 (2A13) (io), 88 I/O66 (2A14) (io), 89 I/O67 (2A15) (io), 91 I/O68 (2D13) (io), 92 I/O69 (2D12) (io), 93 I/O70 (2D11) (io), 94 I/O71 (2D8) (io), 95 I/O72 (2D7) (io), 96 I/O73 (2D4) (io), 97 I/O74 (2D3) (io), 98 I/O75 (2D2) (io), 103 I/O76 (3D2) (io), 104 I/O77 (3D3) (io), 105 I/O78 (3D4) (io), 106 I/O79 (3D7) (io), 107 I/O80 (3D8) (io), 108 I/O81 (3D11) (io), 109 I/O82 (3D12) (io), 110 I/O83 (3D13) (io), 112 I/O84 (3A13) (io), 113 I/O85 (3A12) (io), 114 I/O86 (3A11) (io), 115 I/O87 (3A8) (io), 116 I/O88 (3A7) (io), 117 I/O89 (3A4) (io), 118 I/O90 (3A3) (io), 119 I/O91 (3A2) (io), 123 I/O92 (3B2) (io), 124 I/O93 (3B3) (io), 125 I/O94 (3B4) (io), 126 I/O95 (3B7) (io), 127 I/O96 (3B8) (io), 128 I/O97 (3B11) (io), 129 I/O98 (3B12) (io), 130 I/O99 (3B13) (io), 133 I/O100 (4B12) (io), 134 I/O101 (4B11) (io), 135 I/O102 (4B8) (io), 136 I/O103 (4B7) (io), 137 I/O104 (4B4) (io), 138 I/O105 (4B3) (io), 143 I/O106 (4A3) (io), 144 I/O107 (4A4) (io), 145 I/O108 (4A7) (io), 146 I/O109 (4A8) (io), 147 I/O110 (4A11) (io), 148 I/O111 (4A12) (io), 151 I/O112 (0B13) (io), 152 I/O113 (0B12) (io), 153 I/O114 (0B11) (io), 154 I/O115 (0B8) (io), 155 I/O116 (0B7) (io), 156 I/O117 (0B4) (io), 157 I/O118 (0B3) (io), 158 I/O119 (0B2) (io)
part B pins: 1 TDI (in), 10 GND (power), 19 I0/CLK0 (in), 20 VCC (power), 21 GND (power), 22 I1/CLK1 (in), 31 GND (power), 40 TCK (in), 41 GND (power), 42 VCC (power), 51 GND (power), 52 VCC (power), 59 VCC (power), 60 GND (power), 61 GND (power), 62 VCC (power), 69 VCC (power), 70 GND (power), 79 VCC (power), 80 GND (power), 81 TMS (in), 90 GND (power), 99 I2/CLK2 (in), 100 VCC (power), 101 GND (power), 102 I3/CLK3 (in), 111 GND (power), 120 TDO (out), 121 GND (power), 122 VCC (power), 131 GND (power), 132 VCC (power), 139 VCC (power), 140 GND (power), 141 GND (power), 142 VCC (power), 149 VCC (power), 150 GND (power), 159 VCC (power), 160 GND (power)

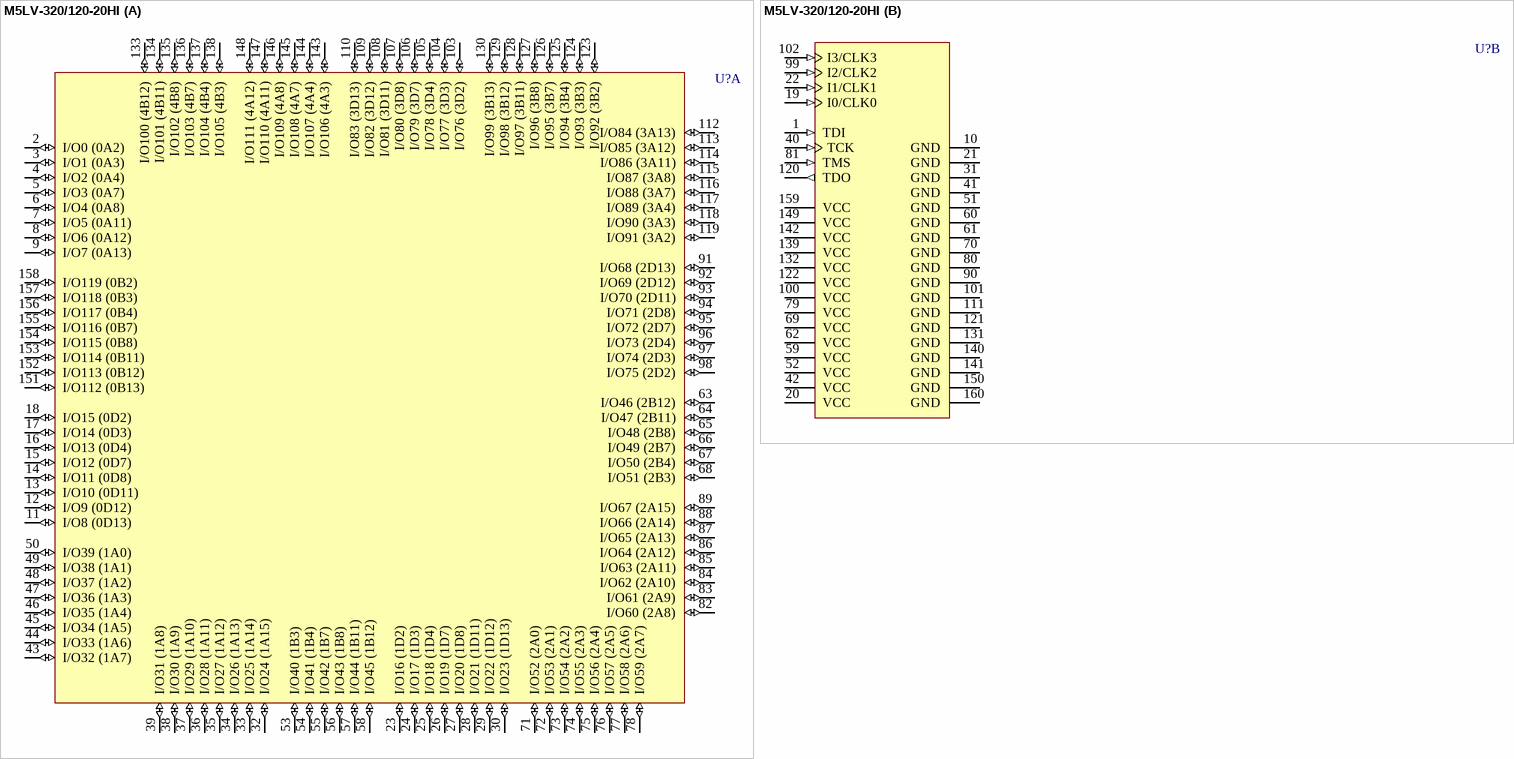
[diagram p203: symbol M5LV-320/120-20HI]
